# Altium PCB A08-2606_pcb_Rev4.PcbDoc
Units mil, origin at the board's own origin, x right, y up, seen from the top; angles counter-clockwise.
Board outline 1181.16 x 1930.8 mil, 6 copper layers (Top Electrical, Ground Plane (GND), Inner Layer 1, Inner Layer 2, Power Plane (VCC), Bottom Electrical), stack 51.068 mil thick; 77 components, 49 nets, 270 pads, 163 vias.
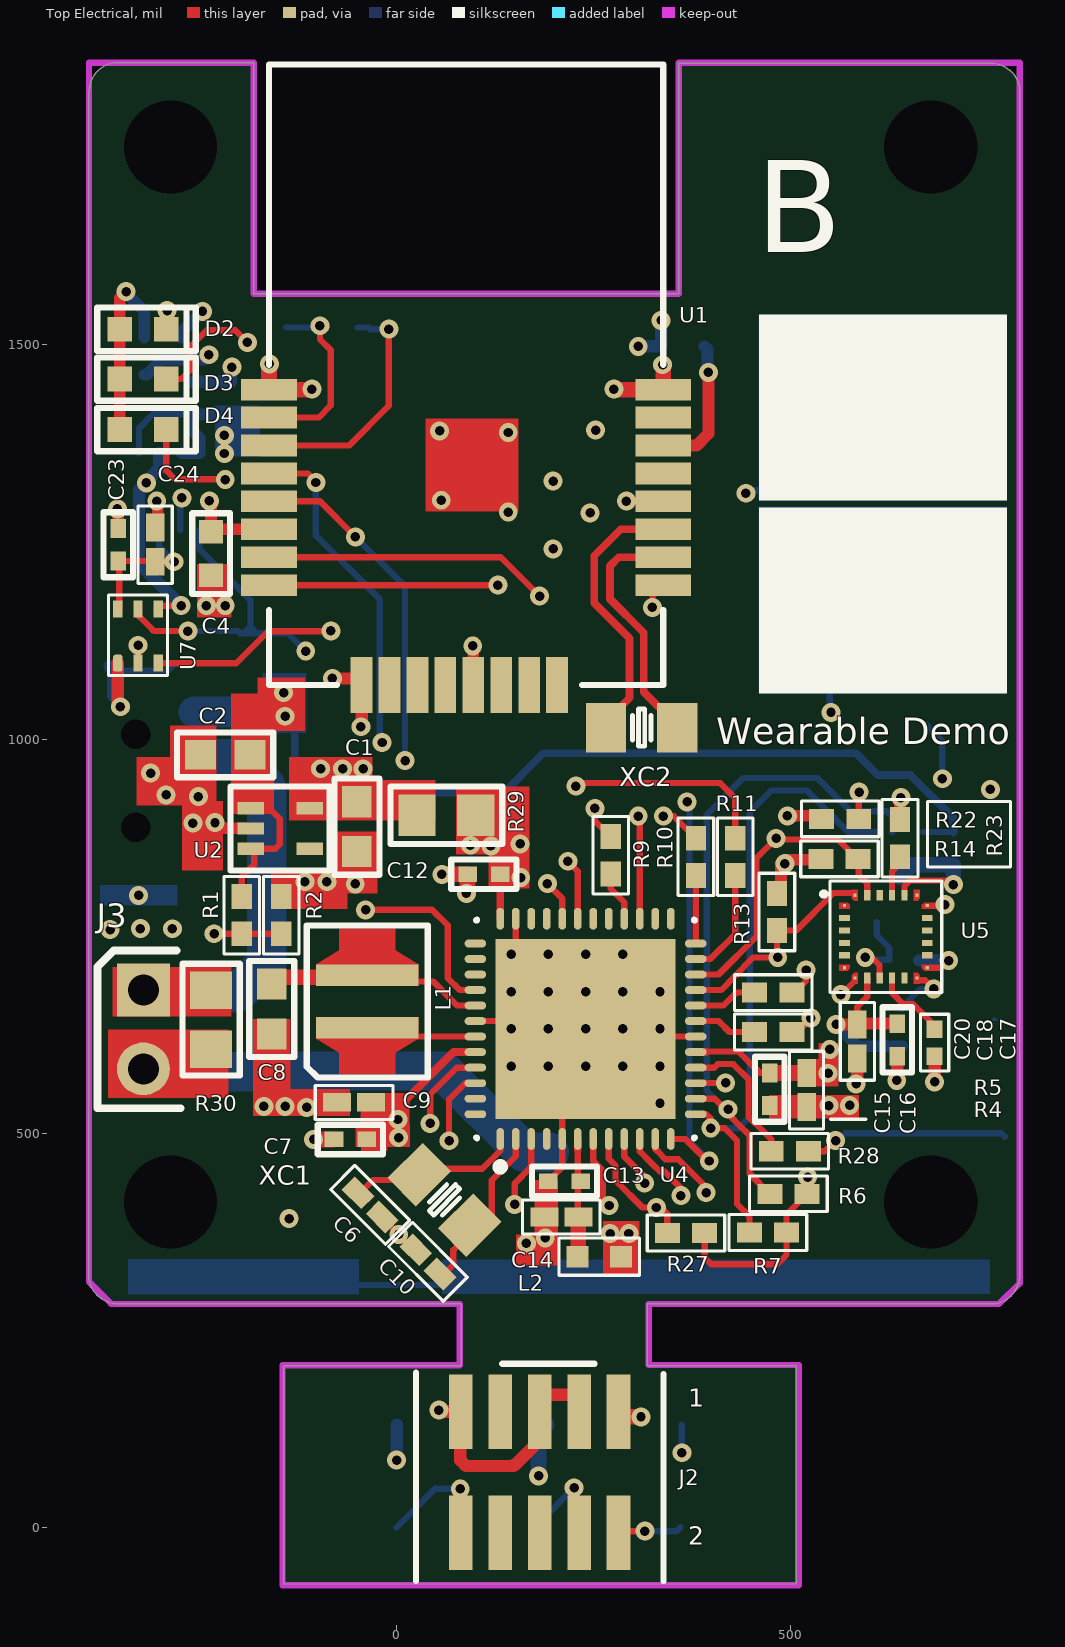
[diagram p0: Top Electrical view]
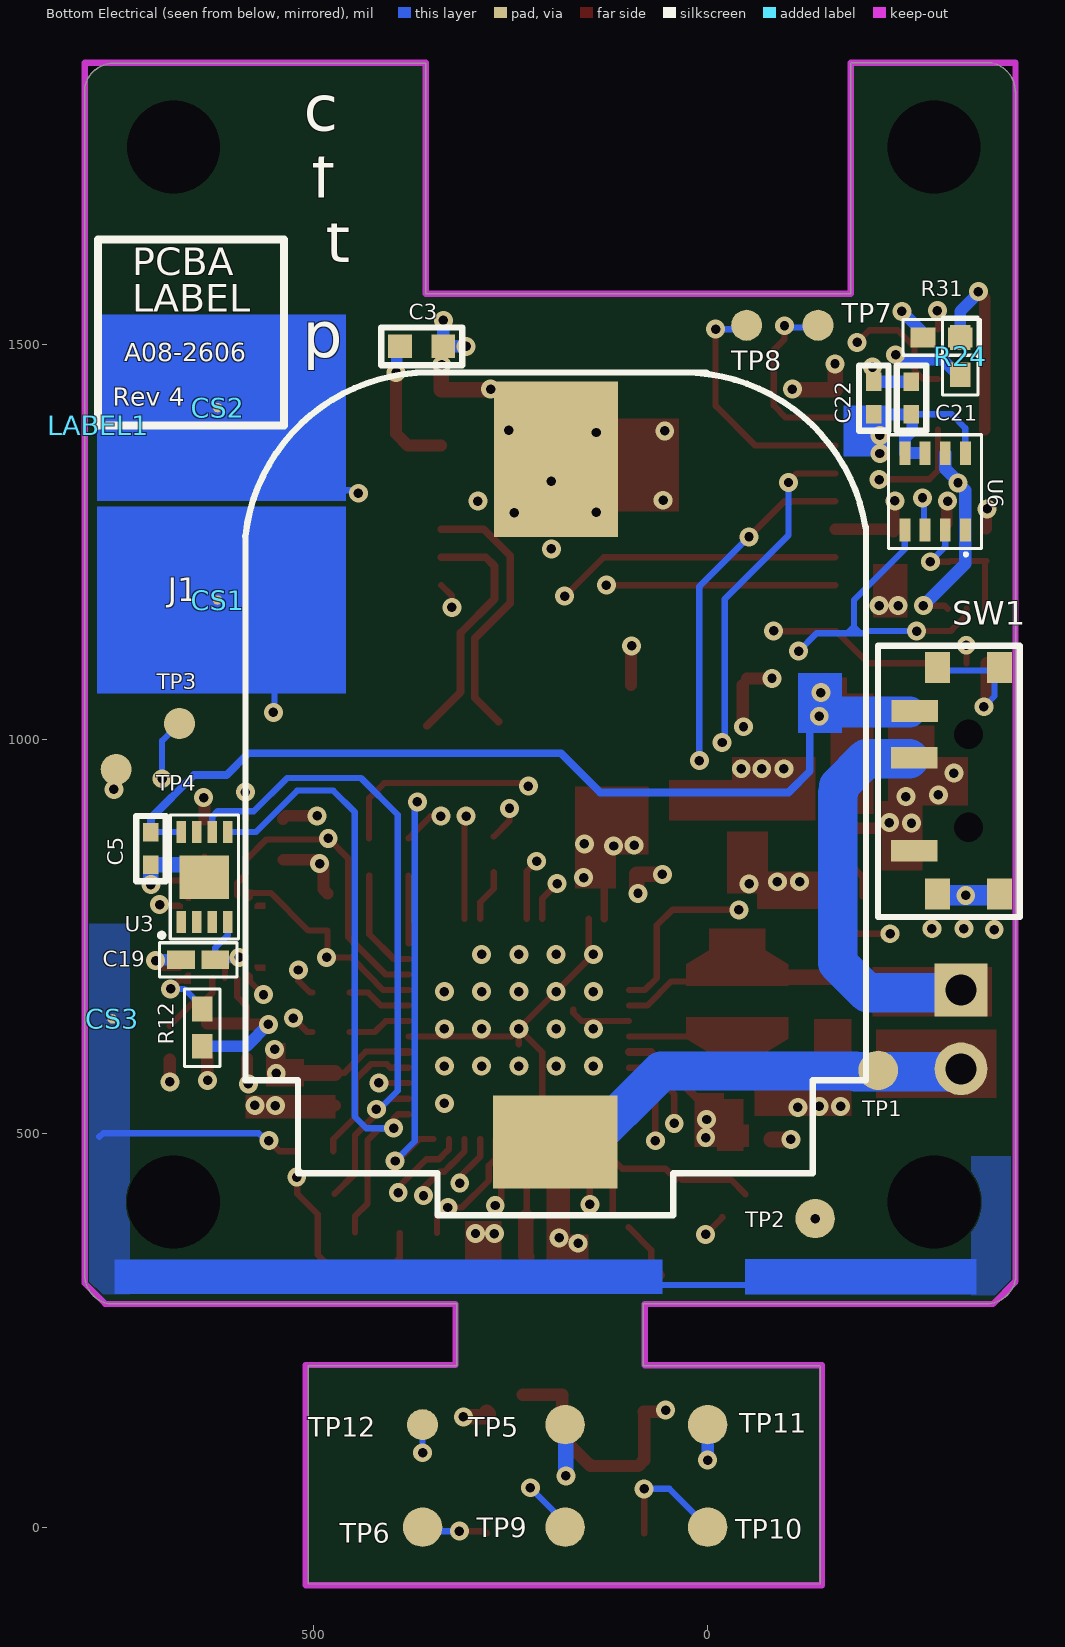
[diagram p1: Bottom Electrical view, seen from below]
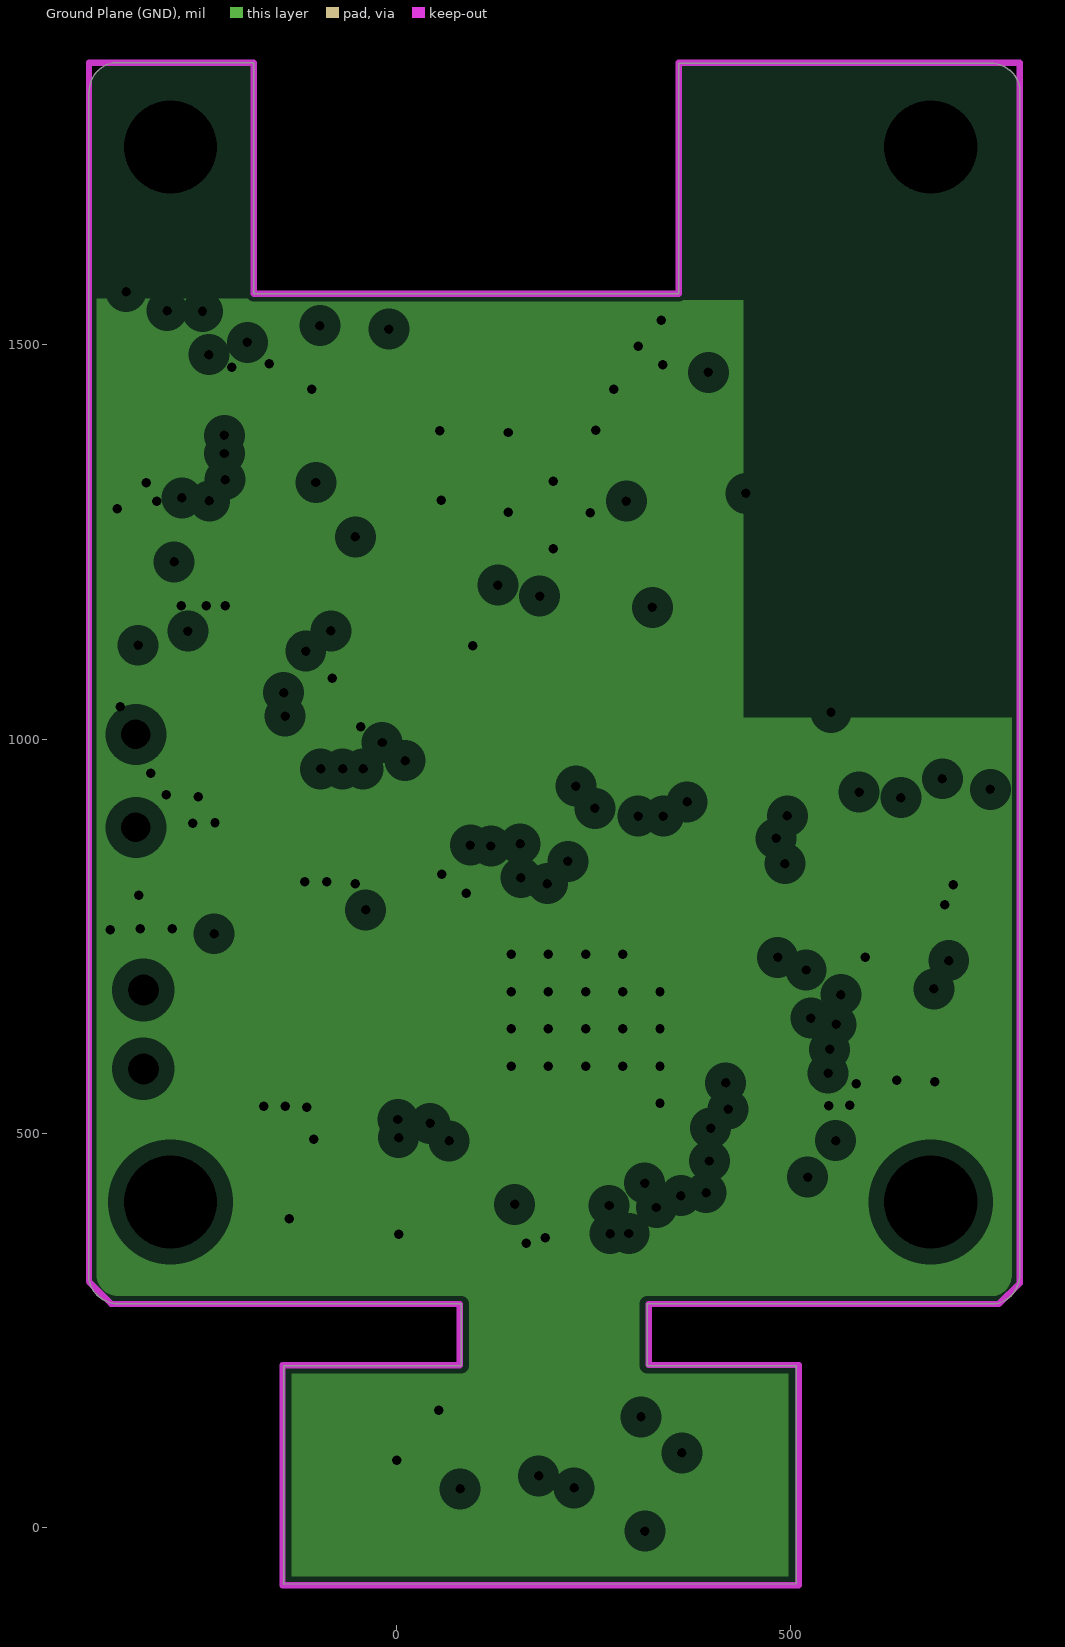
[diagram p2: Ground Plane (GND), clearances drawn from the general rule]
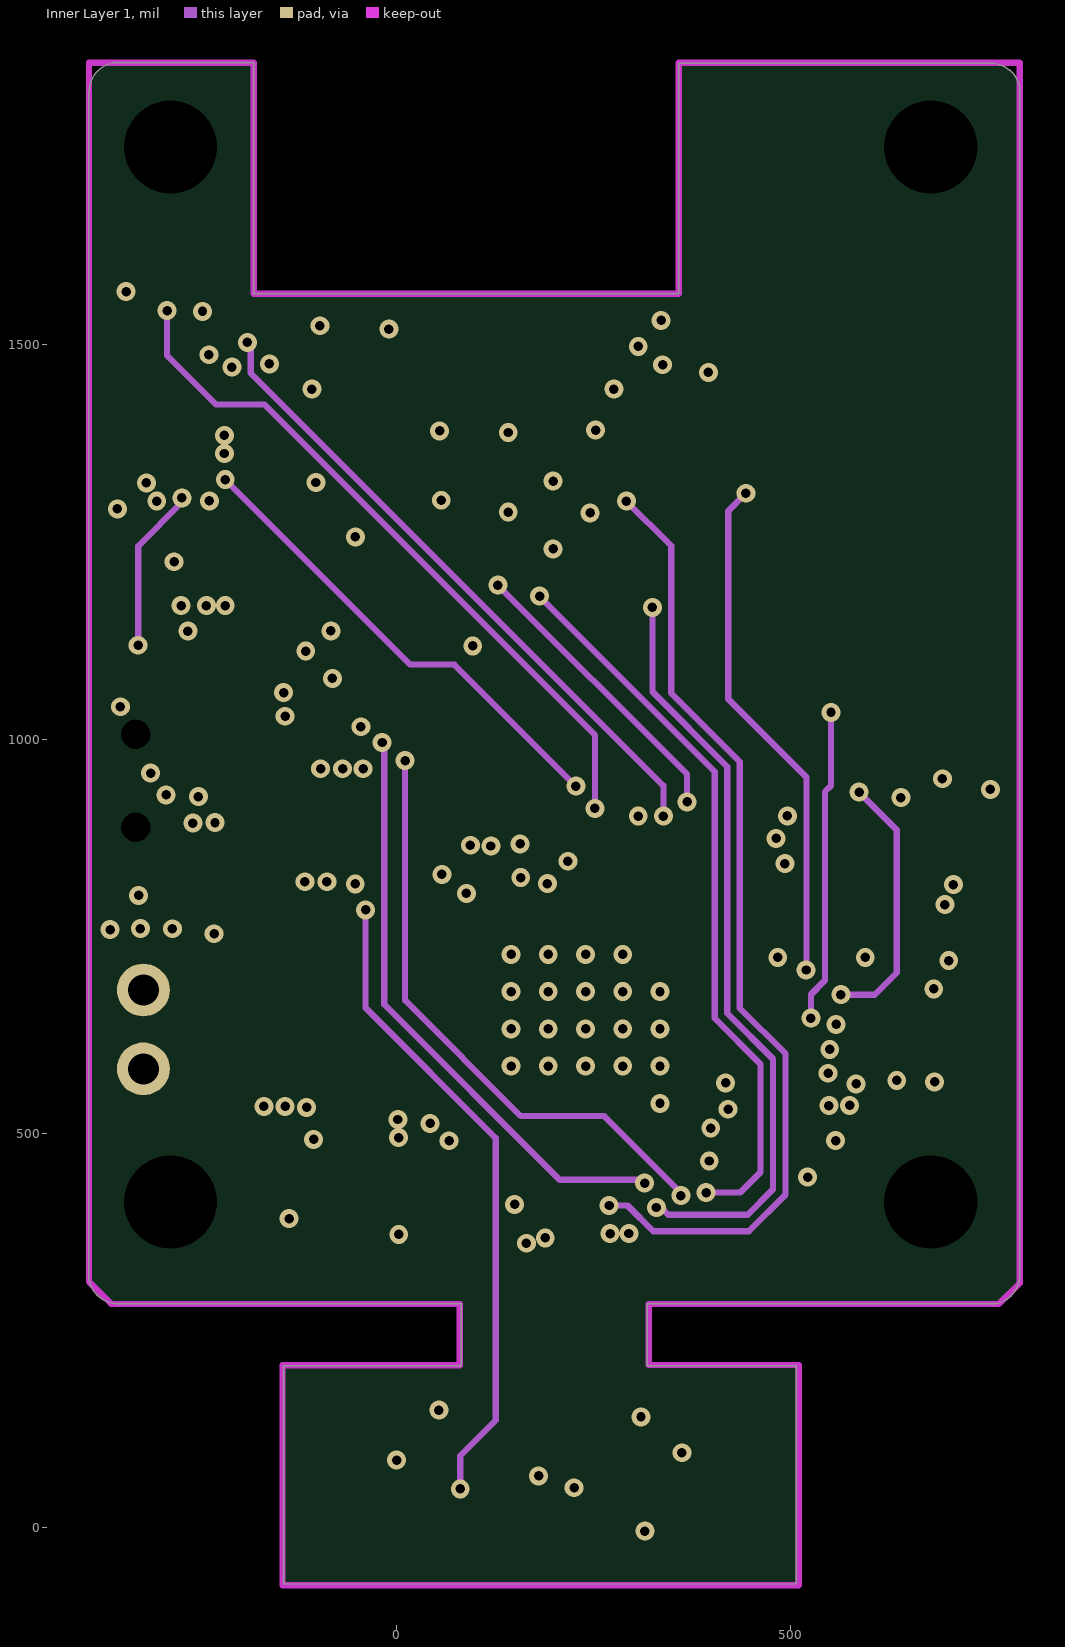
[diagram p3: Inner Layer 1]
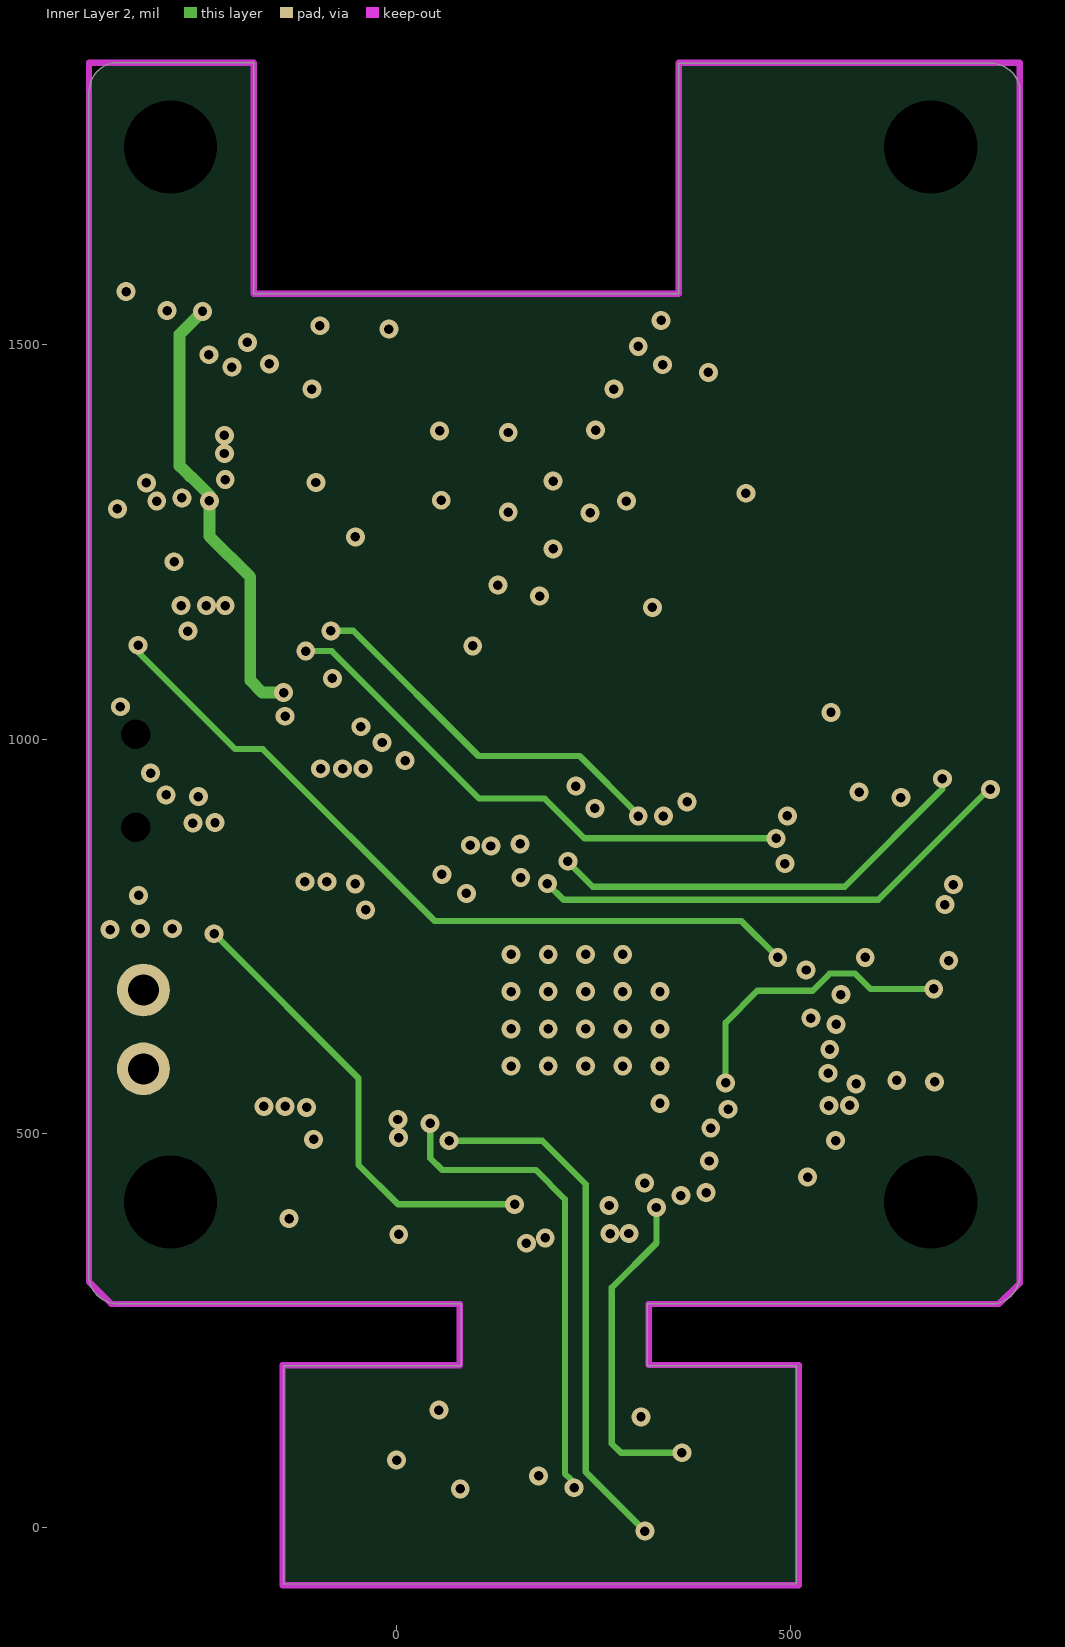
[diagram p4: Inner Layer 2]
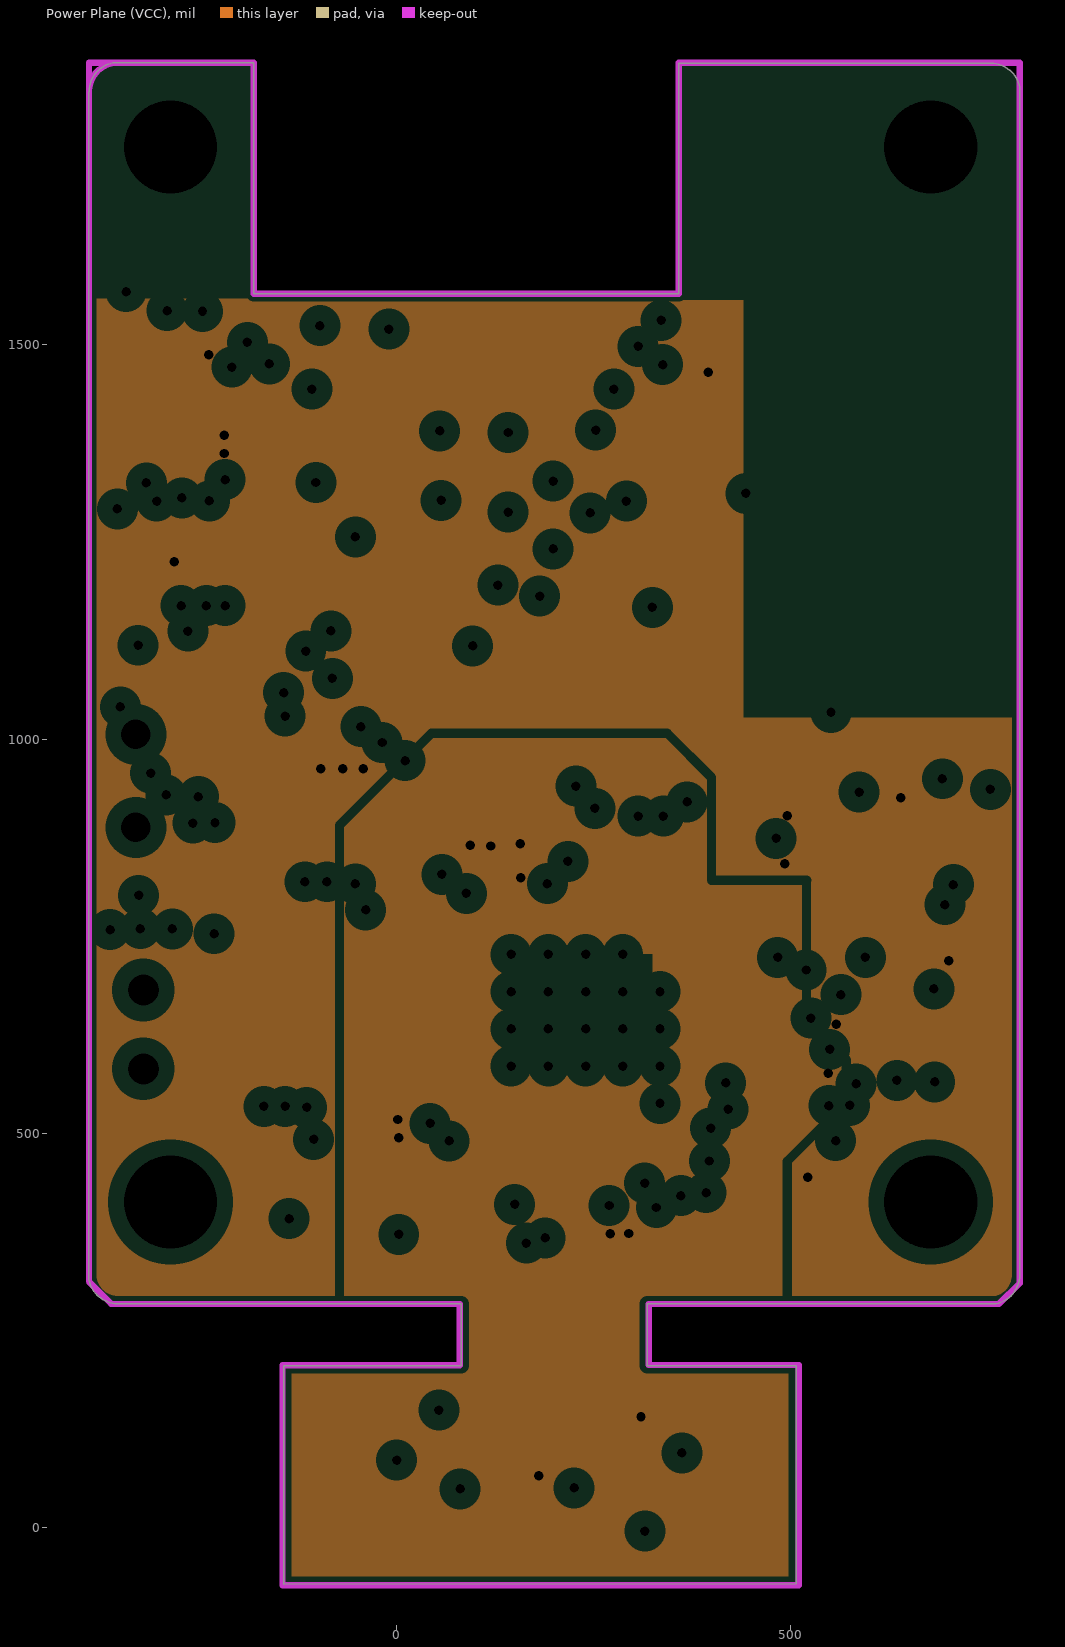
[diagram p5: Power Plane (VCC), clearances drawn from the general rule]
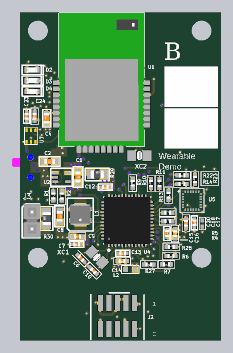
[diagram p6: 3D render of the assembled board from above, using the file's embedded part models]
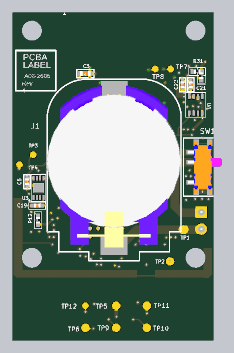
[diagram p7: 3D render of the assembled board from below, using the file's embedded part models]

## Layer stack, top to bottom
Top Solder: solder mask 0.4, Solder Resist, Dk 3.5
Top Electrical: signal copper 1.4
Dielectric 1: core 12.6, FR-4, Dk 4.8
Ground Plane (GND): plane copper 1.417, net GND
Dielectric 3: prepreg 5, Dk 4.2
Inner Layer 1: signal copper 1.417
Dielectric 6: core 10, Dk 4.2
Inner Layer 2: signal copper 1.417
Dielectric 5: prepreg 5, Dk 4.2
Power Plane (VCC): plane copper 1.417, net (Multiple Nets)
Dielectric 4: core 10, Dk 4.2
Bottom Electrical: signal copper 1.4
Bottom Solder: solder mask 0.4, Solder Resist, Dk 3.5

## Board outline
-143.03,-72.54 -143.03,204.72 81.89,204.72 81.89,283.46 -353.73,283.46 -354.22,283.57 cw(c-353.72,321.07) -390.5,313.71 -390.55,313.71 -390.55,1821.6 -390.39,1821.6 cw(c-352.89,1821.1) -360.25,1857.87 -360.25,1858.27 -181.56,1858.27 -181.56,1564.96 357.81,1564.96 357.81,1857.48 754.33,1857.48 754.28,1857.38 cw(c753.78,1819.88) 790.55,1827.23 790.61,1827.6 790.61,320.1 790.5,319.6 cw(c753,320.1) 760.36,283.32 760.61,283.46 318.11,283.46 318.11,204.72 506.93,204.72 506.93,-71.75

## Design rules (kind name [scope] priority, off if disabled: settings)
Clearance Clearance_1 [InComponent('SW1') vs (OnLayer('Keep-Out Layer'))] p1: gap=0
Clearance SW1 [InComponent('SW1') vs (OnLayer('Keep-Out Layer'))] p2: gap=5
Clearance Y9 [InNamedPolygon('PROX')] p3: gap=2
Clearance GYRO [HasFootprint('AP6-00470')] p4: gap=7.56
Clearance "LED CLEARENCE" [HasFootprint('LED')] p5: gap=1
Clearance [All] p6: gap=7.87
ComponentClearance [All] p1 off: gap=10 collisioncheckmode=3 verticalgap=10 showdistances=FALSE
HoleSize [All] p1 off: absolutevalues=TRUE maxlimit=137.8 minlimit=3.94 maxpercent=80.000 minpercent=20.000
MinimumSolderMaskSliver [All] p1 off: minsoldermaskwidth=10
PlaneClearance [All] p1: clearance=20
PlaneConnect [All] p1: planeconnectstyle=Direct reliefexpansion=20 reliefentries=4 reliefconductorwidth=10 reliefairgap=10
PolygonConnect [All] p1: connectstyle=Direct reliefconductorwidth=10 reliefentries=4 polygonreliefangle="90 Angle" airgapwidth=10
RoutingVias [All] p1: holewidth=12 width=24 viastyle="Through Hole" minholewidth=12 minwidth=24 maxholewidth=28 maxwidth=50
SilkToBoardRegionClearance [All] p1 off:
SilkToSilkClearance [All] p1 off: silktosilkclearance=10
SilkToSolderMaskClearance [IsPad] p1 off: minsilkscreentomaskgap=10 clearancetoexposedcopper=TRUE
SolderMaskExpansion [All] p1: expansion=4
Width [All] p1: maxlimit=100 minlimit=6 preferedwidth=8
22 further rules are at their usual default settings.

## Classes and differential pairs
component class "U_SAML21 Wearable Demo__BTLC_CRYPTO_PWR": C1 C2 C3 C4 C5 J1 J3 R1 R2 R27 R30 SW1 TP1 TP2 TP7 TP8 TP12 U1 U2 U3 XC2
component class "U_SAML21 Wearable Demo__MCU&Touch": C6 C7 C8 C9 C10 C12 C13 C14 C15 C16 CS1 CS2 CS3 D2 D3 D4 J2 L1 L2 R4 R5 R6 R7 R9 R10 R11 R24 R28 R29 R31 TP3 TP4 TP5 TP6 TP9 TP10 TP11 U4 XC1
component class "U_SAML21 Wearable Demo__MEMS_Sensors": C17 C18 C19 C20 C21 C22 C23 C24 R12 R13 R14 R22 R23 TP16 TP17 TP18 TP19 TP20 U5 U6 U7
component class "SAML21 Wearable Demo_Top Level": LABEL1

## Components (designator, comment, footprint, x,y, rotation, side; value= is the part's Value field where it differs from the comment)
C1 "CAP-NONPOL" AP1-00002 -50.5,888.93 r270 top
C2 "CAP-NONPOL" AP1-00002 -217.55,979.93 r180 top
C3 "Close to Pin22(VDDIO)of U101" AP1-00039 362.95,1498.27 r0 bottom
C4 "Close to Pin22(VDDIO)of U101" AP1-00039 -235.55,1235.43 r90 top
C5 "CAP-NONPOL" AP1-00038 706.45,860.93 r90 bottom
C6 "CAP-NONPOL" AP1-00001 -33.71,408.91 r315 top
C7 "CAP-NONPOL" AP1-00038 -58.83,491.93 r0 top
C8 "CAP-NONPOL" AP1-00002 -158.5,657.43 r270 top
C9 "Recommended by Escatec. No datasheet available yet." AP1-00001 -54.15,538.93 r180 top
C10 "CAP-NONPOL" AP1-00001 39.61,336.6 r135 top
C12 "CAP-NONPOL" AP1-00038 110.61,828.48 r0 top
C13 "CAP-NONPOL" AP1-00038 212.85,438.8 r0 top
C14 "Recommended by Escatec. No datasheet available yet." AP1-00001 208.95,393.48 r180 top
C15 "CAP-NONPOL" AP1-00038 473.2,555.65 r90 top
C16 "Recommended by Escatec. No datasheet available yet." AP1-00001 520.05,554.66 r270 top
C17 "For Zigbit" AP1-00034 682.47,614.72 r270 top
C18 "CAP-NONPOL" AP1-00038 635.12,618.29 r90 top
C19 "Recommended by Escatec. No datasheet available yet." AP1-00001 646.45,719.93 r180 bottom
C20 "Recommended by Escatec. No datasheet available yet." AP1-00001 584.5,616.27 r270 top
C21 "CAP-NONPOL" AP1-00038 -258.55,1432.6 r270 bottom
C22 "CAP-NONPOL" AP1-00038 -210.55,1432.6 r270 bottom
C23 "CAP-NONPOL" AP1-00038 -353.29,1246.49 r270 top
C24 "Recommended by Escatec. No datasheet available yet." AP1-00001 -306.5,1246.58 r90 top
CS1 "PCB implemented component only. Not to be mounted." AP8-01013#1 50076.87,50856.38 r0 top
CS2 "PCB implemented component only. Not to be mounted." AP8-01013#1 50076.87,51100.47 r0 top
CS3 "PCB implemented component only. Not to be mounted." AP8-01013#2 50370.43,50204.27 r0 top
D2 "APT1608LSECK-J3-PRV" AP4-00017 -321.91,1520 r180 top
D3 "APT1608LSYCK-J3-PRV" AP4-00017 -321.91,1456.71 r180 top
D4 "APT1608LSECK-J4-PRV" AP4-00017 -321.91,1392.6 r180 top
J1 "Element14-Order Code: 2064724" AP8-01011 192.91,921.9 r270 bottom
J2 "HEADER 2x5" AP8-00109 181.45,69.67 r180 top locked
J3 "#NAME?" AP8-00733 -321.39,631.6 r270 top locked
L1 "INDUCTOR" AP3-00115 -37.43,666.99 r90 top
L2 "" AP3-00005 257.01,343.27 r180 top
LABEL1 "PCBA_LABEL" AP9-00049 773.61,1397.6 r180 bottom
R1 "R2" AP2-00000 -196.55,776.55 r270 top
R2 "R2" AP2-00000 -146.55,776.55 r90 top
R4 "R2" AP2-00000 477.78,628.28 r0 top
R5 "R2" AP2-00000 477.78,678.28 r0 top
R6 "R2" AP2-00000 497.07,422.93 r180 top
R7 "R2" AP2-00000 471.07,373.93 r180 top
R9 "R2" AP2-00000 271.5,852.55 r90 top
R10 "R2" AP2-00000 379.61,850.48 r90 top
R11 "R2" AP2-00000 429.61,850.48 r90 top
R12 "R2" AP2-00000 641.37,633.88 r90 bottom
R13 "R2" AP2-00000 482.45,780.55 r270 top
R14 "R2" AP2-00000 561.83,847.93 r0 top
R22 "R2" AP2-00000 562.61,898.6 r180 top
R23 "R2" AP2-00000 638.61,874.22 r90 top
R24 "R2" AP2-00000 -320.39,1485.92 r270 bottom
R27 "R2" AP2-00000 367.07,373.27 r180 top
R28 "R2" AP2-00000 498.83,476.93 r0 top
R29 "R2" AP2-00002 63.01,903.27 r0 top
R30 "R2" AP2-00002 -235.5,643.93 r90 top
R31 "R2" AP2-00000 -296.77,1509.54 r0 bottom
SW1 "SW_SPDT" AP8-01012 -261.99,976.38 r90 bottom locked
TP1 "TESTPOINT" AP8-00010#1 -216.39,579.6 r180 bottom
TP2 "TESTPOINT" AP8-00010#1 -136.39,391.6 r0 bottom
TP3 "TESTPOINT" AP8-00010#2 670.28,1019.69 r180 bottom
TP4 "TESTPOINT" AP8-00010#2 750.59,961.42 r180 bottom
TP5 "TESTPOINT" AP8-00010#3 184,130 r90 bottom
TP6 "TESTPOINT" AP8-00010#1 361.81,0 r90 bottom
TP7 "TESTPOINT" AP8-00010#2 -139.96,1525 r90 bottom
TP8 "TESTPOINT" AP8-00010#2 -49.41,1525 r90 bottom
TP9 "TESTPOINT" AP8-00010#1 180.91,0 r90 bottom
TP10 "TESTPOINT" AP8-00010#1 0,0 r90 bottom
TP11 "TESTPOINT" AP8-00010#1 0,130 r90 bottom
TP12 "TESTPOINT" AP8-00010#2 361.81,130 r90 bottom
U1 "BTLC1000 module" AP9-00141 338.13,1195.28 r90 top locked
U2 "NCP512" AP6-00012 -147.96,886.52 r0 top
U3 "ATECC508A-I2C" AP6-00409 638.61,824.84 r90 bottom
U4 "SAML21G18BM" AP6-00322 239.58,632.3 r90 top
U5 "BHI160" AP6-00470 620.66,749.17 r0 top locked
U6 "Operating range -40â€|+85 Â°C, 0â€|100 % rel. humidity, 300â€|1100 hPa" AP6-00469 -288.55,1313.93 r270 bottom
U7 "VEML6030" PCBComponent_1 -353.88,1096.22 r90 top
XC1 "power = drive level" AP7-00048 60.45,415.46 r315 top
XC2 "power = drive level" AP7-00048 311.16,1014.48 r180 top

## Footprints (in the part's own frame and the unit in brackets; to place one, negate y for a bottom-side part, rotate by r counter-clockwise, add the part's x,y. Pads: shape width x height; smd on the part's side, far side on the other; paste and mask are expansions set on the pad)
AP1-00001 [mm] "Standard 0402 SMD capacitor footprint"
  rect 0.9x0.6 smd: 1(-0.55,0) 2(0.55,0)
  silkscreen extent -1.25,-0.55 1.25,0.55, body extent -0.5,-0.3 0.5,0.3, height 0.2
AP1-00002 [mm]
  rect 1x0.95 smd: 1(-0.8,0) 2(0.8,0)
  silkscreen extent -1.55,-0.73 1.55,0.72, body extent -0.8,-0.4 0.8,0.4, height 0.3
AP1-00034 [mm] "0402_SMD"
  rect 0.56x0.51 smd paste+0 mask+0.05: 1(-0.435,0) 2(0.435,0)
  silkscreen extent -0.91,-0.46 0.91,0.46
AP1-00038 [mm] "Generic pad 0402, spacing 0.45mm"
  rect 0.6x0.5 smd: 1(-0.525,0) 2(0.525,0)
  silkscreen extent -1.05,-0.47 1.05,0.47, body extent -0.5,-0.3 0.5,0.3, height 0.2
AP1-00039 [mil] "Capacitor 0603 Hight 0.8mm"
  rect 30x30 smd: 1(-27.5,0) 2(27.5,0)
  silkscreen extent -52,-24 51,24, body extent -31,-16 32,16, height 12
AP2-00000 [mm] "Standard 0402 SMD resistor footprint"
  rect 0.8x0.65 smd: 1(-0.6,0) 2(0.6,0)
  silkscreen extent -1.25,-0.58 1.25,0.58, body extent -0.5,-0.3 0.5,0.3, height 0.2
AP2-00002 [mm]
  rect 1.2x1.35 smd: 1(-0.95,0) 2(0.95,0)
  silkscreen extent -1.8,-0.92 1.8,0.92, body extent -1,-0.62 1,0.63, height 0.78
AP3-00005 [mm]
  rect 0.7x0.7 smd: 1(-0.7,0) 2(0.7,0)
  silkscreen extent -1.3,-0.6 1.3,0.6, body extent -0.82,-0.41 0.83,0.41, height 0.8
AP3-00115 [mm] "SMD Chip Inductor LQH3NPN_J0 Series (1212 Size)"
  rect 0.7x3.3 smd: 1(-0.85,0) 2(0.85,0)
  Top Electrical region: -0.5,1.65 -1.2,1.65 -1.65,0.9 -1.65,-0.9 -1.2,-1.65 -0.5,-1.65
  Top Electrical region: 0.5,-1.65 1.2,-1.65 1.65,-0.9 1.65,0.9 1.2,1.65 0.5,1.65
  Top Electrical region: -1.625,0.9 -2.35,0.9 -2.35,-0.9 -1.625,-0.9
  Top Electrical region: 1.625,-0.9 2.35,-0.9 2.35,0.9 1.625,0.9
  silkscreen extent -2.45,-1.95 2.45,1.95, body extent -1.5,-1.5 1.5,1.5, height 1.1
AP4-00017 [mm]
  rect 0.8x0.8 smd: 1(-0.75,0) 2(0.75,0)
  silkscreen extent -1.7,-0.7 1.48,0.7, body extent -0.84,-0.35 0.81,0.37, height 0.68
AP6-00012 [mm]
  rect 0.85x0.4 smd: 1(-0.95,0.65) 2(-0.95,0) 3(-0.95,-0.65) 4(0.95,-0.65) 5(0.95,0.65)
  silkscreen extent -1.6,-1.35 1.6,1.35, body extent -0.67,-1.1 0.67,1.1, height 1.1
AP6-00322 [mm] "QFN48_7x7mm_5.8x5.8mm_Paddle"
  oval 0.7x0.25 smd: 1(-3.55,2.75) 2(-3.55,2.25) 3(-3.55,1.75) 4(-3.55,1.25) 5(-3.55,0.75) 6(-3.55,0.25) 7(-3.55,-0.25) 8(-3.55,-0.75) 9(-3.55,-1.25) 10(-3.55,-1.75) 11(-3.55,-2.25) 12(-3.55,-2.75) 25(3.55,-2.75) 26(3.55,-2.25) 27(3.55,-1.75) 28(3.55,-1.25) 29(3.55,-0.75) 30(3.55,-0.25) 31(3.55,0.25) 32(3.55,0.75) 33(3.55,1.25) 34(3.55,1.75) 35(3.55,2.25) 36(3.55,2.75)
  oval 0.25x0.7 smd: 13(-2.75,-3.55) 14(-2.25,-3.55) 15(-1.75,-3.55) 16(-1.25,-3.55) 17(-0.75,-3.55) 18(-0.25,-3.55) 19(0.25,-3.55) 20(0.75,-3.55) 21(1.25,-3.55) 22(1.75,-3.55) 23(2.25,-3.55) 24(2.75,-3.55) 37(2.75,3.55) 38(2.25,3.55) 39(1.75,3.55) 40(1.25,3.55) 41(0.75,3.55) 42(0.25,3.55) 43(-0.25,3.55) 44(-0.75,3.55) 45(-1.25,3.55) 46(-1.75,3.55) 47(-2.25,3.55) 48(-2.75,3.55)
  rect 5.8x5.8 smd: 49(0,0)
  silkscreen extent -4.57,-3.52 3.52,3.52, body extent -3.51,-3.51 3.51,3.51, height 0.78
AP6-00409 [mm]
  rect 0.7x0.3 smd mask+0.075: 1(-1.45,0.75) 2(-1.45,0.25) 3(-1.45,-0.25) 4(-1.45,-0.75) 5(1.45,-0.75) 6(1.45,-0.25) 7(1.45,0.25) 8(1.45,0.75)
  rect 1.4x1.6 smd paste-0.025 mask+0.075: 9(0,0)
  silkscreen extent -2,-1.1 2,1.45, body extent -1.55,-1.05 1.55,1.05, height 0.6
AP6-00469 [mm] "LGA_2.5 mm x 2.5 mm x 0.93 mm metal lid"
  rect 0.75x0.35 smd: 1(1.235,0.975) 2(1.235,0.325) 3(1.235,-0.325) 4(1.235,-0.975) 5(-1.235,-0.975) 6(-1.235,-0.325) 7(-1.235,0.325) 8(-1.235,0.975)
  silkscreen extent -1.84,-1.5 2.07,1.5, body extent -1.25,-1.25 1.25,1.25, height 1
AP6-00470 [mm] "LGA_24_3.0X3.0X.95"
  rect 0.1x0.1 smd mask+0: 1(-1.335,1) 6(-1.335,-1) 7(-1,-1.335) 12(1,-1.335) 13(1.335,-1) 18(1.335,1) 19(1,1.335) 24(-1,1.335)
  rect 0.35x0.2 smd mask+0: 2(-1.335,0.6) 3(-1.335,0.2) 4(-1.335,-0.2) 5(-1.335,-0.6) 14(1.335,-0.6) 15(1.335,-0.2) 16(1.335,0.2) 17(1.335,0.6)
  rect 0.2x0.35 smd mask+0: 8(-0.6,-1.335) 9(-0.2,-1.335) 10(0.2,-1.335) 11(0.6,-1.335) 20(0.6,1.335) 21(0.2,1.335) 22(-0.2,1.335) 23(-0.6,1.335)
  Top Electrical region: -1.1,-1.51 -1.1,-1.236 -1.024,-1.16 -0.9,-1.16 -0.9,-1.51
  Top Electrical region: -1.51,-1.1 -1.236,-1.1 -1.16,-1.024 -1.16,-0.9 -1.51,-0.9
  Top Electrical region: 1.1,-1.51 1.1,-1.236 1.024,-1.16 0.9,-1.16 0.9,-1.51
  Top Electrical region: 1.51,-1.1 1.236,-1.1 1.16,-1.024 1.16,-0.9 1.51,-0.9
  Top Electrical region: 1.51,1.1 1.236,1.1 1.16,1.024 1.16,0.9 1.51,0.9
  Top Electrical region: 1.1,1.51 1.1,1.236 1.024,1.16 0.9,1.16 0.9,1.51
  Top Electrical region: -1.1,1.51 -1.1,1.236 -1.024,1.16 -0.9,1.16 -0.9,1.51
  Top Electrical region: -1.51,1.1 -1.236,1.1 -1.16,1.024 -1.16,0.9 -1.51,0.9
  silkscreen extent -2.03,-1.8 1.8,1.8, body extent -1.55,-1.55 1.55,1.55, height 1
AP7-00048 [mm] "CFPX  32.768kHz Crystal mini"
  rect 1.3x1.6 smd: 1(-1.143,0) 2(1.157,0)
  silkscreen extent -0.29,-0.6 0.31,0.6, body extent -1.6,-0.77 1.6,0.72, height 0.77
AP8-00010#1 [mil] "Testpad 50mil"
  round 50 smd paste-25: 1(0,0)
AP8-00010#2 [mil] "Testpad 50mil"
  round 39.37 smd paste-25: 1(0,0)
AP8-00010#3 [mil] "Testpad 50mil"
  round 50 smd paste-25: 1(0,-3.09)
AP8-00109 [mm]
  rect 0.76x2.4 smd: 1(-2.54,-1.95) 2(-2.54,1.95) 3(-1.27,-1.95) 4(-1.27,1.95) 5(0,-1.95) 6(0,1.95) 7(1.27,-1.95) 8(1.27,1.95) 9(2.54,-1.95) 10(2.54,1.95)
  silkscreen extent -3.99,-3.21 3.99,3.5, body extent -3.81,-3 3.81,3
AP8-00733 [mm] "Pin header 1x2 Pin in Paste"
  rect 1.7x1.7 / inner round 1.7 / far side rect 1.7x1.7 hole 1: 1(-1.27,0)
  rect 2.1x2.1 on Top Paste: 1(-1.27,0) 2(1.27,0)
  round 1.7 hole 1: 2(1.27,0)
  silkscreen extent -2.54,-1.48 2.54,1.19, body extent -2.54,-1.27 2.54,1.27, height 8.38
AP8-01011 [mm] "Coin cell Battery Holder 24.9X15.6X5.3"
  rect 5x4 smd mask+0: 1(-11,0.012)
  rect 3x4 smd mask+0: 2(11,-0.012)
  silkscreen extent -13.8,-10 13.36,10, body extent -12.88,-10.01 11.38,9.96, height 5.4
AP8-01012 [mm]
  round 0.5 hole 0.95 mask+0: 0(-2.25,-1.75) 0(0.75,-1.75)
  rect 0.7x1.5 smd mask+0: 1(0,0) 2(1.5,-0.023) 3(-3,0)
  rect 1x0.8 smd mask+0: 4(-4.4,-2.75) 4(-4.4,-0.75) 4(2.9,-0.75) 4(2.9,-2.75)
  silkscreen extent -5.13,-3.4 3.61,1.17, body extent -4.6,-4.53 3.1,0.47, height 1.4
AP8-01013#1 [mil] "Capacitive Touch Button 8x6MM"
  round 12 smd far side paste-12 mask+0: 1(-49455,-49680)
  Bottom Electrical region: -49617.48,-49561.89 -49617.48,-49798.11 -49302.52,-49798.11 -49302.52,-49561.89
AP8-01013#2 [mil] "Capacitive Touch Button 8x6MM"
  round 12 smd far side paste-12 mask+0: 1(-49614.98,-49559.39)
  Bottom Electrical region: -49617.48,-49561.89 -49617.48,-49561.89 -49612.48,-49556.89 -49607.48,-49561.89
AP9-00049 [mil] "Placement area for 6x6mm sticker"
  silkscreen extent 0,0 236,236
AP9-00141 [mm] "BTLC 1000 Module"
  rect 0.7x1.8 smd: 1(6.3,12.7) 2(5.4,12.7) 3(4.5,12.7) 4(3.6,12.7) 5(2.7,12.7) 6(1.8,12.7) 7(0.9,12.7) 8(0,12.7) 17(0,0) 18(0.9,0) 19(1.8,0) 20(2.7,0) 21(3.6,0) 22(4.5,0) 23(5.4,0) 24(6.3,0)
  rect 1.8x0.7 smd: 9(-3.22,9.72) 10(-3.22,8.82) 11(-3.22,7.92) 12(-3.22,7.02) 13(-3.22,6.12) 14(-3.22,5.22) 15(-3.22,4.32) 16(-3.22,3.42)
  Top Electrical region: 2.37,4.659 5.37,4.659 5.37,7.659 2.37,7.659
  silkscreen extent -3.22,0 16.78,12.7, body extent -3.22,0 16.78,12.7, height 4.4
PCBComponent_1 [mm]
  rrect50% 0.2x0.2 on Top Overlay paste-0.305 mask+0: 1(0,0.5)
  rrect50% 0.55x0.3 smd paste-0.305 mask+0: 1(0,0)
  rect 0.55x0.3 smd paste-0.305 mask+0: 2(0,-0.65) 3(0,-1.3) 4(1.75,-1.3) 5(1.75,-0.65) 6(1.75,0)
  silkscreen extent -0.4,-1.6 2.2,0.3

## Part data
C1 C2 C8: library part A01-0268, "Ceramic capacitor, SMD 0603, X5R, 6.3V, ±10%"
C3 C4: library part A01-0491, "Ceramic capacitor, SMD 0603, X5R, 16V, 10UF ± 20% (High Density)"
C5 C7 C12 C13 C15 C18 C21 C22 C23: library part A01-0352, "Ceramic capacitor, SMD 0402, X7R, 16V, +/-10% (de19761)"
C6 C10: library part A01-0013, "Ceramic capacitor, SMD 0402, NP0, 50V, +/-5%"
C9 C14 C16 C19 C20 C24: library part A01-0347, "Ceramic capacitor, SMD 0402, X5R, 6.3V, +/-20% (de33687)"
C17: library part A01-0334, "Ceramic Capacitors - SMD0402 6.3V, 470nF, 10%, X5R"
CS1 CS2 CS3: library part A08-2605, "Capacitive Touch Button 8x6MM"
D2: library part A10-0187, "LED RED CLEAR 0603 SMD_Rectangle with Flat Top, 1.10mm x 0.80mm"
D3: library part A10-0188, "1.85V_Rectangle with Flat Top, 1.10mm x 0.80mm_LED YELLOW CLEAR 0603 SMD"
D4: library part A10-0189, "1.8V_LED ORANGE CLEAR 0603 SMD_1.60mm L x 0.80mm W"
J1: library part A08-2603, "Battery Holder, SMT, 20 mm"
J2: library part A08-0022, "2x5 pin header, 1.27mm pitch, SMD"
J3: library part A08-1754, "1x2 pin header, 2.54mm pitch, Pin-in-Paste THM"
L1: library part A03-0191, "10uH power inductor, Isat = 560mA , Itemp = 710mA, Rdc = 0.360ohm"
L2: library part A03-0035, "SMD RF inductor 0603. Z=470Ohm (@100MHz), Max R(dc)=0.65Ohm, Max current=1A"
LABEL1: library part A09-0612, "PCBA identification label PP Top White Gloss"
R1 R2 R6 R7 R12 R13 R14 R22 R23: library part A02-0228, "Thick film resistor, SMD 0402, 1/16W, 1%"
R4 R5 R28: library part A02-0212, "Thick film resistor, SMD 0402, 1/16W, 1%"
R9 R10 R11: library part A02-0206, "Thick film resistor, SMD 0402, 1/16W, 1%"
R24 R31: library part A02-0163, "RES 0.0 OHM 1/16W 0402 SMD"
R27: library part A02-0260, "Thick film resistor, SMD 0402, 1/16W, 1%"
R29 R30: library part A02-0285, "Thick film resistor, SMD 0805, 0.125W, 1%"
SW1: library part A08-2604, "Slide Switches SPDT HORZ GRND 1.5mm"
TP1 TP2 TP3 TP4 TP5 TP6 TP7 TP8 TP9 TP10 TP11 TP12: library part A08-0004, "Single SMD testpad"
U1: library part A06-1298, "Bluetooth module, 24pin, chip Antenna, with shield, with MAC"
U2: library part A06-1426, "1.8V 80 mA CMOS Low Iq Voltage Regulator"
U3: library part A06-1281, "ATECC508A with an I2C Interface and a 8 Pin UDFN Package with Paddle"
U4: library part A06-1358, "Atmel 32-bit RISC MCU 48pin QFN"
U5: library part A06-1427, "Ultra-low power sensor hub inc.integrated IMU(GYRO)"
U6: library part A06-1425, "Humidity and pressure sensor"
U7: "IC,Sensor: UV + ALS"
XC1 XC2: library part A07-0056, "32.768kHz KX-327NHT, 3.2 x 1.5 mm SMD 20ppm (de19774)"

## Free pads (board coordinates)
  round 0 hole 118.11 unplated mask+0: MH(-286.96,412.6) MH(-286.95,1751.18) MH(677.61,412.6) MH(677.61,1751.18)

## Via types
v1: diameter 24, hole 12, Top Electrical to Bottom Electrical, tented both sides, 143 vias
v2: diameter 24, hole 12, Top Electrical to Bottom Electrical, tented top, 20 vias

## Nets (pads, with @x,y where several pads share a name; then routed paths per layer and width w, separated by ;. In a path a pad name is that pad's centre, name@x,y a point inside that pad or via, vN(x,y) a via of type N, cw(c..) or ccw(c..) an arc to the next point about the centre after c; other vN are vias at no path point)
BAT_SENSE: R1.2 R2.1 U4.3 | length 763.6
  Top Electrical w8: v1(-231.55,752.93) R1.2 R2.1@-147.55,752.93 ; v1(149.61,409.6) 149.61,436.03 170.68,457.11 U4.3
  Inner Layer 2 w8: v1(-231.55,752.93) -48.55,569.93 -48.55,459.76 1.61,409.6 v1(149.61,409.6)
BLE_CTS_MCU_RTS: U1.7 U4.11 | length 1394.9
  Top Electrical w8: U1.7 132.01,1230.71 v1(181.45,1181.27) ; U4.11 328.17,479.61 330.43,477.35 331.06,477.35 331.06,476.72 340.89,466.88 346.53,466.88 357.09,466.88 392.61,431.36 v1(392.61,424.6)
  Inner Layer 1 w8: v1(181.45,1181.27) 181.45,1180.37 403.45,958.37 403.45,645.66 461.64,587.46 461.64,450.46 435.78,424.6 v1(392.61,424.6)
BLE_EN: R27.2 TP12.1 U1.17 U4.8 | length 1617
  Top Electrical w8: U4.8 269.11,467.53 273.44,463.2 273.39,463.14 277.73,458.8 277.73,439.71 311.84,405.6 v1(329.61,405.6) 335.61,405.6 343.45,397.76 R27.2 ; v1(324.5,1166.93) 324.5,1181.65 U1.17
  Inner Layer 1 w8: v1(324.5,1166.93) 324.5,1059.76 419.57,964.69 419.57,853 419.5,852.93 419.5,652.05 477.52,594.04 477.52,428.65 445.44,396.57 344.64,396.57 335.61,405.6 v1(329.61,405.6)
  Inner Layer 2 w8: v1(329.61,405.6) 329.61,360.61 273,304 273,106 284.63,94.37 v1(361.81,94.37)
  Bottom Electrical w8: v1(361.81,94.37) TP12.1
BLE_RTS_MCU_CTS: U1.8 U4.12 | length 1191.7
  Top Electrical w8: U1.8 v1(128.45,1195.27) ; U4.12 366.18,492.53 v1@395.36,463.35
  Inner Layer 1 w8: v1(128.45,1195.27) 368.45,955.27 v1(368.45,920.27)
  Bottom Electrical w8: v1(368.45,920.27) 371.61,917.11 371.61,489.6 v1(396.61,464.6)
BLE_RX_MCU_TX: U1.4 U4.9 | length 1252.7
  Top Electrical w8: U1.4 -112.8,1337.01 -102.39,1326.6 v1@-102.39,1322.6 ; U4.9 288.8,470.29 319.61,439.48 316.72,436.6 v1(314.61,436.6)
  Inner Layer 1 w8: v1(-18.39,995.6) -15.68,992.88 -15.68,663.25 206.63,440.94 310.26,440.94 v1(314.61,436.6)
  Bottom Electrical w8: v1(-102.52,1325.47) -102.52,1258.72 -21.52,1177.72 v1@-21.52,1003.72
BLE_TX_MCU_RX: U1.5 U4.10 | length 1294
  Top Electrical w8: U1.5 -97.37,1301.57 v1(-52.39,1256.6) ; U4.10 308.48,476.72 323.73,461.47 323.85,461.47 334.32,451.01 339.96,451.01 360.61,430.36 v1(360.61,420.6)
  Inner Layer 1 w8: v1(10.61,972.6) 10.61,668.6 157.61,521.6 263.37,521.6 360.61,424.36 v1(360.61,420.6)
  Bottom Electrical w8: v1(-52.39,1256.6) 10.61,1193.6 v1(10.61,972.6)
BLE_WKUP: U1.20 U4.7 | length 1312.9
  Top Electrical w8: U4.7 249.43,464.66 261.86,452.23 261.86,415.82 v1(269.54,408.14)
  Inner Layer 1 w8: v1(269.54,408.14) 292.83,408.14 325.37,375.6 446.92,375.6 493.39,422.07 493.39,600.61 435.38,658.63 435.38,846.35 435.45,846.42 435.45,971.27 348.38,1058.34 348.38,1245.05 v1(291.5,1301.93)
CRYPTO_SCL: R6.2 U3.6 U4.14 | length 859.4
  Top Electrical w8: U4.14 403.54,543.72 415.99,531.27 422.45,531.27 422.45,522.39 435.45,509.39 447.58,497.26 447.58,448.79 R6.2
  Bottom Electrical w8: v1(420.45,530.27) 416.99,530.27 393.43,553.83 393.43,904.12 439.9,950.6 533.61,950.6 575.81,908.39 621.98,908.39 628.76,901.61 U3.6
CRYPTO_SDA: R7.2 U3.5 U4.13 | length 833
  Top Electrical w8: U4.13 392.92,524.03 398.45,518.5 v1(398.45,506.27) 416.13,506.27 431.71,490.68 431.71,410.5 447.61,394.6 447.61,374.09 R7.2
  Bottom Electrical w8: v1(398.45,506.27) 433.27,506.27 447.97,520.97 447.97,907.48 475.09,934.6 520.61,934.6 573.28,881.93 U3.5
DEBUG_RXD: TP4.1 U4.32 | length 681
  Top Electrical w8: v1(191.16,816.54) 210.06,797.64 U4.32
  Inner Layer 2 w8: v1(191.16,816.54) 211.63,796.06 610.84,796.06 751,936.22 v1(753.36,936.22)
DEBUG_TXD: TP3.1 U4.31 | length 710.6
  Top Electrical w8: v1(217.14,844.88) 229.74,832.28 U4.31
  Inner Layer 2 w8: v1(217.14,844.88) 217.14,844.09 248.64,812.6 568.32,812.6 692.32,936.6 v1(692.32,949.61)
  Bottom Electrical w8: TP3.1 692.32,997.64 v1(692.32,949.61)
GND: C1.2 C2.2 C3.1 C4.1 C5.1 C6.2 C7.1 C8.2 C9.2 C10.2 C12.1 C13.1 C14.2 C15.1 C16.2 C17.2 C18.1 C19.2 C20.2 C21.1 C22.1 C23.1 C24.2 J1.1 J2.3 J2.5 J2.9 R2.2 SW1.4 TP2.1 TP11.1 U1.1 U1.9 U1.13 U1.24 U2.2 U3.4 U3.9 U4.5 U4.18 U4.35 U4.42 U4.49 U5.9 U5.18 U5.20 U6.1 U6.7 U7.1@-353.88,1096.22 U7.4 | length 2788.5
  Top Electrical w7.6: v1(594.55,723.06) 602.54,723.06 612.34,713.27 612.34,703.48 U5.9@612.79,703.03 ; U5.9 U5.9@612.79,703.03 ; 612.79,708.21 U5.9@612.79,703.03
  Top Electrical w7.87: C6.2 -18.39,392.6 v1(2.61,371.6) ; U5.20 644.28,813.07 651.81,820.6 701.12,820.6 v1(706.45,815.27)
  Top Electrical w8: U7.4@-304.67,1165.12 -300.52,1169.27 v1(-273.55,1169.27) ; v1(57.45,828.27) v1@57.66,828.48 ; v1(88.45,804.27) 89.45,804.27 v1@89.94,803.78 ; v1(96.45,1118.27) 96.45,1120.87 96.5,1120.93 v1@97.18,1120.25 ; U4.42 159.74,642.14 170.45,652.85 U4.49@170.45,656.93 ; U4.35 151,720.88 v2(239.58,632.3) ; C13.1 210.06,456.67 U4.5 210.06,602.77 v2(239.58,632.3) ; U4.49@239.58,612.61 v2(239.58,632.3) ; U4.18 249.43,622.46 v2(239.58,632.3) ; U5.18 v1@699.89,788.54
  Top Electrical w15: C23.1 v1@-353.29,1290.72 ; C24.2@-303.29,1273.07 v1@-303.29,1300.72 ; v1(-230.55,893.93) -230.55,890.98 v1@-227.09,887.52 ; v1@-227.09,886.73 U2.2@-187.43,886.73 ; v1@-105.5,533.8 C9.2@-81.13,533.8 ; v1(-81.55,1076.93) U1.9@-49.55,1076.93 ; C7.1@-80.5,491.93 C7.1@-79.5,490.93 ; v1(-52.55,816.27) -52.55,817.87 -50.5,819.93 C1.2 ; U1.13 v1@97.18,1120.25 ; v1(188.45,366.93) 187.3,368.08 C14.2 C14.2@192.18,398.36
  Top Electrical w15.75: U7.1@-353.88,1096.22 -353.88,1044.31 v1(-350.5,1040.93) ; v1(-241.55,1169.27) -243.21,1169.27 -245.55,1171.61 -238.89,1178.27 v1@-234.55,1173.93 ; v1(-45.39,1015.6) -44.55,1016.44 U1.9 ; v1(53.45,148.46) 55.47,146.44 J2.9 80.61,145.6 80.61,85 88.01,77.6 146.61,77.6 147.61,78.6 148.61,77.6 180.45,109.44 J2.5@180.45,145.44 ; J2.5@184.45,145.44 184.45,167.81 J2.3@234.45,167.81 ; C15.1 518.08,534.98 C16.2 521.98,534.93 v1(548.45,534.93) ; v1@584.5,560.66 C20.2 ; v1(634.5,566.93) 634.73,566.93 635.12,567.32 C18.1 ; v1@682.47,564.96 C17.2@682.47,593.07
  Top Electrical w20: v1(-161.5,1475.93) -161.87,1475.55 U1.1 -108.12,1443.31 v1(-107.5,1443.93) ; v1(-105.5,491.93) C7.1@-80.5,491.93 ; v1@57.66,828.48 C12.1 v1@89.94,803.78 ; C14.2@192.18,398.36 C13.1 ; v1(275.5,1443.93) 276.13,1443.31 U1.24 338.13,1474.31 v1(337.5,1474.93)
  Bottom Electrical w7.6: SW1.4@-363.92,1091.68 SW1.4@-363.92,1086.73 ; v1(-350.5,1040.93) -363.92,1054.35 SW1.4@-363.92,1086.73 ; SW1.4@-285.18,1091.68 -290.13,1086.73 SW1.4@-363.92,1086.73
  Bottom Electrical w8: v1(-273.55,1169.27) -268.89,1169.27 v1@-268.68,1169.05 ; v1@593.45,719.93 C19.2 624.79,735.25 609.08,750.96 U3.4
  Bottom Electrical w15.75: SW1.4@-364.39,1092.16 SW1.4@-363.92,1091.68 ; U6.7 -301.35,1343.13 -315.55,1328.93 -315.55,1326.93 v1(-317.55,1324.93) -326.94,1315.54 U6.1 -326.94,1222.65 v1(-273.55,1169.27) ; C21.1 C22.1 -210.55,1470.36 v1(-209.12,1471.8) -209.12,1474.05 v1@-207.39,1475.77 ; v1(0,85) TP11.1 ; v1(306.45,1498.27) C3.1 v1(335.45,1531.27)
  Bottom Electrical w19.68: U3.9 654.03,840.26 C5.1 v1(706.45,815.27)
  other v1: 164.45,360.27 -136.39,391.6 -114.39,532.6 -168.55,533.93 -141.55,533.93 574.66,535.06 582.83,562.33 682.5,564.93 -363.55,758.27 -325.14,759.57 -284.55,759.27 695.45,789.93 -327.39,801.6 -116.5,818.93 -88.5,818.93 -258.55,893.27 -251.55,926.93 -292.58,929.13 -312.27,956.69 -217.55,1169.27 198.45,1241.27 245.5,1286.93 141.5,1287.93 -354.5,1291.93 -304.5,1301.93 56.5,1302.93 198.45,1327.27 141.5,1388.93 54.5,1390.93 252.5,1391.93
  other v2: 334.07,537.81 145.09,585.05 192.34,585.05 239.58,585.05 286.83,585.05 334.07,585.05 145.09,632.3 192.34,632.3 286.83,632.3 334.07,632.3 145.09,679.54 192.34,679.54 239.58,679.54 286.83,679.54 334.07,679.54 145.09,726.79 192.34,726.79 239.58,726.79 286.83,726.79
LED0: R11.1 U4.23 | length 137.7
  Top Electrical w8: U4.23 398.01,720.88 429.61,752.48 R11.1
LED1: R10.1 U4.24 | length 86.4
  Top Electrical w8: U4.24 379.35,764.93 379.61,765.19 R10.1
LED2: R9.1 U4.28 | length 66
  Top Electrical w8: R9.1@271.5,830.93 271.5,810.22 288.8,792.93 U4.28
MCU_VCC: C7.2 C9.1 C12.2 C15.2 C16.1 J2.1 L2.1 R29.2 TP5.1 U4.17 U4.36 U4.44 | length 689.6
  Top Electrical w8: -38.16,524.27 C9.1@-28.63,533.8 ; v1@278.45,368.27 284.57,362.15 L2.1 ; U4.17@392.57,602.77 392.57,603.46 433.76,603.46 460.91,576.32 C15.2 ; v1@547.06,576.31 v1(547.45,575.93)
  Top Electrical w10: C9.1@-28.63,533.8 3.13,533.8 72.1,602.77 U4.44 ; v1(93.45,865.27) 123.19,865.27 123.5,865.58 160.61,828.48 C12.2 ; U4.36 131.32,826.91 C12.2@132.46,828.05 ; U4.17 U4.17@392.57,602.77
  Top Electrical w15: C7.2@-38.16,485.93 -38.16,524.27
  Top Electrical w20: J2.1@280.45,145.44 278.61,143.6 282.21,140 v1(310,140) ; C15.2 C16.1 v1@547.06,576.31
  Bottom Electrical w20: v1(180,65) 180,120 TP5.1@190,130
  other v1: 270.68,372.44 294.61,372.6 2.45,494.27 1.45,517.27 549.45,606.27 157.45,824.27 119.45,864.27 156.5,866.93
NetC17_1: C17.1 U5.10 | length 90
  Top Electrical w8: U5.10 628.54,677.71 642.65,663.6 655.25,663.6 C17.1@682.47,636.38
NetD2_1: D2.1 R9.2 | length 960.6
  Top Electrical w7.87: D2.1 -292.39,1542.61 v1(-291.39,1543.6) ; v1(251.5,911.93) 251.5,896.17 R9.2
  Inner Layer 1 w7.87: v1(-291.39,1543.6) -291.39,1486.6 -229.39,1424.6 -167.97,1424.6 -64.69,1321.31 -64.6,1321.31
  Inner Layer 1 w8: -64.6,1321.31 251.5,1005.21 v1(251.5,911.93)
NetD2_2: D2.2 D3.2 D4.2 R24.1 R31.1 | length 245.9
  Top Electrical w15: D4.2 D3.2 D2.2 -351.44,1559.55 v1(-343.39,1567.6)
  Bottom Electrical w15: v1(-343.39,1567.6) -343.39,1565.6 -320.39,1542.6 R24.1
NetD3_1: D3.1 R10.2 | length 1024.7
  Top Electrical w7.87: D3.1 -273.28,1456.71 -262.2,1467.79 -262.2,1497.46 -241.07,1518.6 -204.88,1518.6 v1(-189.55,1503.27) ; v1(338.45,902.27) 351.44,902.27 R10.2
  Inner Layer 1 w7.87: v1(-189.55,1503.27) -185.31,1499.02 -185.31,1464.38 338.45,940.63 v1(338.45,902.27)
NetD4_1: D4.1 R11.2 | length 1000.2
  Top Electrical w7.87: D4.1 -292.39,1340.76 -281.36,1329.74 -218.02,1329.74 v1(-217.55,1329.27) ; v1(227.45,940.27) 231.26,944.08 410.64,944.08 429.61,925.11 R11.2
  Inner Layer 1 w7.87: v1(-217.55,1329.27) 17.19,1094.52 73.19,1094.52 v1(227.45,940.27)
NetJ1_2: J1.2 J3.2@-321.39,581.6 R30.1 TP1.1 | length 567.1
  Bottom Electrical w50: J3.2@-325.5,577.93 -325.5,578.8 J3.2@-318.6,578.8 ; J3.2@-321.39,581.6 J3.2@-318.6,578.8 ; J1.2@193.41,475.83 161.89,475.83 58.91,578.8 -187.14,578.8 -188.01,577.93 -317.72,577.93 J3.2@-318.6,578.8
NetJ3_1: J3.1@-321.39,681.6 R30.2 SW1.1 | length 505.4
  Bottom Electrical w50: J3.1@-325.5,677.93 -202.82,677.93 -164.91,715.85 -164.91,931.47 -166.3,932.87 -166.3,940.32 -201.13,975.16 SW1.1@-255.97,975.16
NetL1_1: L1.1 U4.43 | length 138.5
  Top Electrical w8: L1.1@-37.43,625.53 -34.35,622.46 U4.43
NetR4_1: R4.1 U4.19 | length 80.6
  Top Electrical w8: U4.19 408.45,642.14 422.31,628.28 R4.1
NetR5_1: R5.1 U4.20 | length 81.6
  Top Electrical w8: U4.20 414.34,661.83 430.78,678.28 R5.1
NetR22_1: R22.1 U5.7 | length 394
  Top Electrical w7: v1(563.61,675.6) 581.29,693.28 U5.7
  Top Electrical w8: R22.1 586.23,929.22 586.61,929.6 v1(586.61,932.6)
  Inner Layer 1 w8: v1(563.61,675.6) 606.61,675.6 634.61,703.6 634.61,884.6 v1(586.61,932.6)
NetR23_1: R23.1 U5.21 | length 53
  Top Electrical w7.87: U5.21 628.54,832.53 638.61,842.6 R23.1
NetR28_1: R28.1 U4.16 | length 206.8
  Top Electrical w8: U4.16 402.91,583.09 407.41,587.59 427.19,587.59 446.32,568.46 446.32,520.97 ; R28.1 475.2,492.09 465.11,502.18 ; 446.32,520.97 465.11,502.18 ; 446.32,520.97 465.11,502.18
NetTP7_1: TP7.1 U1.2 | length 235
  Top Electrical w8: U1.2 -99.02,1407.87 -83.62,1423.27 -83.62,1493.62 -97.44,1507.44 v1(-97.44,1524.41)
  Bottom Electrical w8: TP7.1@-139.96,1522.05 -99.8,1522.05 v1(-97.44,1524.41)
NetTP8_1: TP8.1 U1.3 | length 310.1
  Top Electrical w8: U1.3 -60.43,1372.44 -10.83,1422.05 -10,1422.87 v1(-10,1520)
  Bottom Electrical w8: TP8.1@-49.41,1522.05 -35.24,1522.05 -33.19,1520 v1(-10,1520)
PA00: C6.1 U4.1 XC1.1 | length 215.1
  Top Electrical w8: C6.1@-48.02,422.22 -29.64,440.6 32.19,440.6 XC1.1@36.4,444.81 ; XC1.1@39.89,441.31 53.5,454.93 108.5,454.93 131.32,477.74 U4.1
PA01: C10.1 U4.2 XC1.2 | length 187
  Top Electrical w8: C10.1@57.92,319.29 71.61,332.98 71.61,351.6 100.43,380.42 XC1.2@100.43,380.78 ; XC1.2@120.5,397.29 120.5,440.15 151,470.65 U4.2
R\E\S\E\T\: J2.10 TP10.1 U4.40 | length 1206.2
  Top Electrical w8: v1(-39.55,783.27) -39.34,783.48 44.72,783.48 64.61,763.6 64.61,696.72 79.82,681.51 U4.40 ; J2.10@80.45,-8.1 80.45,48.44 v1(80.61,48.6) ; v1@84.45,48.6 v1@84.45,54.6
  Inner Layer 1 w8: v1(-39.55,783.27) -39.55,658.99 125.73,493.71 125.73,135.73 80.61,90.61 v1(80.61,48.6)
  Bottom Electrical w8: TP10.1 48.6,48.6 v1(80.61,48.6)
RTC_CLKN: U1.19 XC2.2 | length 342.5
  Top Electrical w10: XC2.2@265.61,1022.48 295.61,1052.48 295.61,1127.48 250.61,1172.48 250.61,1232.48 284.27,1266.14 U1.19
RTC_CLKP: U1.18 XC2.1 | length 310.2
  Top Electrical w10: U1.18 281.71,1230.71 270.61,1219.61 270.61,1177.76 313.48,1134.88 313.48,1059.61 XC2.1@356.16,1016.93
SENSOR_AP_INT: R12.2 U4.15 U5.12 | length 500.7
  Top Electrical w7.87: U4.15 v1@409.9,563.4 ; U5.12 660.03,693.99 670.39,693.99 v1(681.45,682.93) ; v1@409.9,563.4 410.21,563.72 v1(417.3,563.72) 416.98,563.4 v1@409.9,563.4
  Inner Layer 2 w7.87: v1(417.3,563.72) 417.3,640.29 457.61,680.6 527.61,680.6 549.34,702.33 581.61,702.33 601.01,682.93 v1(681.45,682.93)
  Bottom Electrical w7.87: R12.2 641.37,659.85 664.45,682.93 v1(681.45,682.93)
SENSOR_I2C_SCL: R14.2 U4.22 U5.23 U6.4 U7.5 | length 1502.8
  Top Electrical w8: U7.5 -328.29,1157.29 -320.48,1149.48 -320.48,1149.37 -313.52,1142.42 -313.42,1142.42 -308,1137 -279,1137 ; U4.22 408.32,701.2 456.45,749.32 456.45,848.93 v1(481.45,873.93) 482.78,872.6 559.78,872.6 585.45,846.93 585.45,850.16 586.41,850.16 586.41,828.02 597.04,817.39 U5.23
  Inner Layer 2 w8: v1(-115.39,1111.6) -82.46,1111.6 104.68,924.46 187.68,924.46 238.21,873.93 v1(481.45,873.93)
  Bottom Electrical w8: v1(-265,1137) -201.28,1137 -198.55,1134.27 ; U6.4 -250.17,1240.88 -185.55,1176.27 -185.55,1142.44 ; -177.38,1134.27 -185.55,1142.44 ; v1(-115.39,1111.6) -138.06,1134.27 -198.55,1134.27 ; -198.55,1134.27 -193.72,1134.27 -185.55,1142.44
SENSOR_I2C_SDA: R13.2 U4.21 U5.24 U6.3 U7.2 | length 1524.8
  Top Electrical w7.87: U7.2 -328.29,1118.71 v1(-328,1119) ; U4.21 411.66,681.51 449.35,719.86 452.41,722.93 v1(483.45,722.93) 482.45,723.93 R13.2 506.65,756.93 554.45,804.73 577.5,804.73
  Inner Layer 1 w7.87: v1(-328,1119) -328,1244.61 -328.07,1244.68 -272.55,1300.2 v1(-272.55,1305.93)
  Inner Layer 2 w7.87: v1(-328,1119) -328,1110.33 -204.87,987.2 -170,987.2 48.09,769.11 437.27,769.11 v1(483.45,722.93)
  Bottom Electrical w7.87: U6.3@-274.55,1265.31 v1@-274.55,1305.93
SENSOR_UV_ALS_INT: U4.27 U7.3 | length 854.6
  Top Electrical w8: U7.3 -203.77,1096.22 -163.19,1136.8 -84.02,1136.8 v1(-83.55,1137.27) ; U4.27 v1@308.48,902.27
  Inner Layer 2 w8: v1(-83.55,1137.27) -55.05,1137.27 103.8,978.42 232.02,978.42 306.56,903.88 v1@308.06,903.88
  other v1: 306.45,902.27
SWCLK: J2.4 TP9.1 U4.45 | length 778.5
  Top Electrical w8: v1(42.45,512.27) 42.45,549.25 76.28,583.09 U4.45
  Inner Layer 2 w8: v1(42.45,512.27) 42.45,468.27 57.45,453.27 176.45,453.27 213.45,416.27 213.45,68 v1@220.67,60.78
  Bottom Electrical w8: TP9.1@181.45,-7.1 181.45,6.45 v1(225,50)
SWDIO: J2.2 TP6.1 U4.46 | length 851.6
  Top Electrical w8: v1(66.45,490.27) 66.45,542.96 86.89,563.4 U4.46 ; J2.2@280.45,-8.1 J2.2@280.45,-7.1 ; J2.2 283.55,-5 v1(315,-5)
  Inner Layer 2 w8: v1(66.45,490.27) 184.73,490.27 240,435 240,70 v1(315,-5)
  Bottom Electrical w8: v1@320,0 v1(315,-5) 355,-5 TP6.1@360,0
VBAT: C2.1 C4.2 C5.2 R1.1 R31.2 SW1.2 U1.6 U2.1 U2.3 U3.8 | length 2047.1
  Top Electrical w8: R1.1 -196.55,824.93 -180.55,840.93 -180.55,860.05 -181.43,860.93 -153.87,860.93 -148.37,866.42 -148.37,898.75 -160.55,910.93
  Top Electrical w15: v1(-237.55,1302.27) -235.89,1302.27 -235.55,1301.93 C4.2 -232.34,1266.14 U1.6
  Top Electrical w39.37: -190.5,1026.93 -183.5,1033.93 -178.5,1028.93
  Inner Layer 2 w15: v1(-246.39,1542.6) -275.39,1513.6 -275.39,1346.6 -262.1,1333.3 -261.21,1333.3 -237.55,1309.64 v1(-237.55,1302.27) -237.55,1257.27 -185.93,1205.64 -185.93,1074.3 -170.55,1058.93 v1(-143.5,1058.93)
  Bottom Electrical w8: v1(-141.5,1028.93) -129.43,1016.86 ; U3.8 706.12,881.93 C5.2
  Bottom Electrical w10: -129.43,1016.86 -129.43,959.14 -102.55,932.27 136.45,932.27 186.11,981.93 582.84,981.93 610.62,954.14 651.98,954.14 706.45,899.67 C5.2
  Bottom Electrical w15: R31.2 -273.15,1515.84 v1(-246.39,1542.6)
  Bottom Electrical w39.37: SW1.2@-256.87,1034.21 -146.78,1034.21 v1(-141.5,1028.93)
VCC: C1.1 C3.2 C18.2 C19.1 C20.1 C21.2 C22.2 C23.2 C24.1 R6.1 R7.1 R12.1 R13.1 R14.1 R22.2 R23.2 R24.2 R27.1 R29.1 U1.22 U2.5 U5.8 U5.13 U6.2 U6.5 U6.6 U6.8 U7.6 | length 1439.1
  Top Electrical w8: C23.2 -307.39,1225.83 C24.1 v1(-282.5,1224.93) ; U7.6@-351.91,1165.12 C23.2@-351.91,1224.45 ; R27.1 390.69,342.02 399.12,333.6 482.69,333.6 494.69,345.6 R7.1 494.69,396.93 R6.1 520.69,447.51 521.46,446.75 v1(521.46,444.09) ; C20.1 584.5,660.5 597.04,673.03 U5.8 ; U5.13 691.32,709.8 v1(700.45,718.93)
  Top Electrical w15: U1.22 380.45,1372.44 395.45,1387.44 v1(395.45,1465.27) ; R13.1 487.65,809.37 487.65,841.93 v1(492.45,841.93) 497.45,846.93 R14.1@538.2,846.93 ; v1(495.61,902.6) 534.98,902.6 R22.2 ; v1(557.5,637.93) C20.1 ; C20.1@585.53,638.96 C18.2 ; R23.2 638.61,919.6 636.61,921.6 638.61,923.6 638.61,924.6 v1(639.61,925.6)
  Bottom Electrical w8: U6.8 -326.94,1394.54 -309.55,1411.93 C21.2 ; U6.2 -301.35,1243.78 v1(-282.5,1224.93)
  Bottom Electrical w15: R24.2 -317.35,1462.29 -298.28,1481.37 -244.62,1481.37 v1(-238.39,1487.6) ; U6.6@-272.55,1362.55 -272.17,1362.93 -250.54,1362.93 U6.5 -250.17,1381.54 -259.55,1390.93 -259.55,1410.93 C21.2 C22.2 -210.55,1387.93 v1@-211.55,1386.93 ; C3.2 394.45,1494.27 394.45,1466.27 v1(395.45,1465.27) ; v1@558.5,638.93 v1(557.5,637.93) 585.18,610.25 R12.1 ; C19.1@662.45,718.93 C19.1@668.1,718.93 ; C19.1 699.45,719.93 v1(700.45,718.93)
  other v1: -96.55,962.27 -68.55,962.27 -42.55,962.27 -218.55,1362.27 -218.55,1385.27
VCC_MCU_VDDANA: C13.2 C14.1 L2.2 U4.6 | length 150.6
  Top Electrical w8: C14.1@229.74,393.48 229.74,478.48
  Top Electrical w10: 229.74,478.48 U4.6
  Top Electrical w19.68: L2.2 230.61,344.43 C14.1 C14.1@229.74,393.48
VDDCORE: C8.1 L1.2 U4.41 | length 266.8
  Top Electrical w8: L1.2@-37.43,692.46 46.04,692.46 76.67,661.83 U4.41
  Top Electrical w19.68: C8.1@-154.87,697.85 L1.2@-38.04,697.85
Y2: CS1.1 R4.2 | length 517.3
  Top Electrical w8: R4.2 508.05,628.28 v1(525.63,645.85)
  Inner Layer 1 w8: v1(525.63,645.85) 525.63,675.91 543.32,693.6 543.32,932.87 551.06,940.6 v1(551.06,1033.86)
  Bottom Electrical w8: 543.61,1118.6 549.61,1112.6 v1@549.61,1033.86
Y3: CS2.1 R5.2 | length 738.4
  Top Electrical w8: R5.2 504.35,678.28 519.45,693.37 v1(519.45,706.93)
  Inner Layer 1 w8: v1(443.13,1311.81) 420.61,1289.29 420.61,1050.83 520,951.43 520,707.9 519.45,707.35 v1(519.45,706.93)
  Bottom Electrical w8: v1(443.13,1311.81) 447.06,1315.75 486.43,1315.75
Y9: CS3.1 R28.2 | length 441.7
  Top Electrical w8: R28.2 543.27,476.93 v1(556.89,490.55) v1@549.73,490.55
  Bottom Electrical w8: -90.55,307.27 77.45,307.27 81.45,303.27 ; v1(556.89,490.55) 560.04,490.55 569.49,500 767.13,500 771.85,495.28
pads on no net: J2.6 J2.7 J2.8 J3.1@-321.39,681.6 J3.2@-321.39,581.6 SW1.0 SW1.3 U1.10 U1.11 U1.12 U1.14 U1.15 U1.16 U1.21 U1.23 U2.4 U3.1 U3.2 U3.3 U3.7 U4.4 U4.25 U4.26 U4.29 U4.30 U4.33 U4.34 U4.37 U4.38 U4.39 U4.47 U4.48 U5.1 U5.2 U5.3 U5.4 U5.5 U5.6 U5.11 U5.14 U5.15 U5.16 U5.17 U5.19 U5.22 U7.1@-373.57,1096.22

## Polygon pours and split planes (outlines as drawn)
Y9 on Bottom Electrical "PROX" (solid, remove dead copper, pour order 4): 784.69,295.28 760.36,295.28 733.51,295.28 733.51,765.35 760.36,765.35 784.69,765.35
Y9 on Bottom Electrical "PROX" (solid, remove dead copper, pour order 5): -385.73,470.68 -334.55,470.68 -334.55,294.49 -385.73,294.49
GND on Ground Plane (GND) (split plane): -188.58,1557.94 -186.52,1556.36 -184.13,1555.37 -181.56,1555.03 357.81,1555.03 360.38,1555.37 362.77,1556.36 364.23,1557.48 440.61,1557.48 440.61,1027.48 780.68,1027.48 780.68,320.38 780.59,319.73 780.62,319.73 780.31,315.77 779.3,311.56 777.64,307.55 775.37,303.85 772.55,300.55 769.25,297.73 765.56,295.47 761.55,293.81 759.82,293.39 318.11,293.39 315.54,293.05 313.15,292.06 311.09,290.48 309.51,288.43 308.52,286.03 308.18,283.46 308.18,204.72 308.52,202.16 309.51,199.76 311.09,197.7 313.15,196.13 315.54,195.14 318.11,194.8 497,194.8 497,-61.83 -133.11,-62.6 -133.11,194.8 81.89,194.8 84.46,195.14 86.85,196.13 88.91,197.7 90.49,199.76 91.48,202.16 91.82,204.72 91.82,283.46 91.48,286.03 90.49,288.43 88.91,290.48 86.85,292.06 84.46,293.05 81.89,293.39 -353.45,293.39 -354.09,293.48 -354.09,293.45 -358.05,293.76 -362.26,294.77 -366.27,296.43 -369.97,298.7 -373.27,301.52 -376.09,304.82 -378.35,308.52 -380.01,312.52 -380.62,315.06 -380.62,1559.05 -189.43,1559.05
MCU_VCC on Power Plane (VCC) (split plane): 393.49,948.8 393.49,820.93 393.69,819.39 394.29,817.95 395.24,816.72 396.47,815.77 397.91,815.18 399.45,814.97 514.05,814.97 514.05,643.37 514.25,641.83 514.6,640.99 514.85,640.4 515.79,639.16 564.49,590.46 564.49,541.74 491.24,468.48 490.29,467.25 490.04,466.65 489.69,465.81 489.49,464.27 489.49,293.39 318.11,293.39 315.54,293.05 313.15,292.06 311.09,290.48 309.51,288.43 308.52,286.03 308.18,283.46 308.18,204.72 308.52,202.16 309.51,199.76 311.09,197.7 313.15,196.13 315.54,195.14 318.11,194.8 497,194.8 497,-61.83 -133.11,-62.6 -133.11,194.8 81.89,194.8 84.46,195.14 86.85,196.13 88.91,197.7 90.49,199.76 91.48,202.16 91.82,204.72 91.82,283.46 91.48,286.03 90.49,288.43 88.91,290.48 86.85,292.06 84.46,293.05 81.89,293.39 -66.54,293.39 -66.54,888.03 46.74,1001.31 340.98,1001.31
VCC on Power Plane (VCC) (split plane): -188.58,1557.94 -186.52,1556.36 -184.13,1555.37 -181.56,1555.03 357.81,1555.03 360.38,1555.37 362.77,1556.36 364.23,1557.48 440.61,1557.48 440.61,1027.48 780.68,1027.48 780.68,320.38 780.59,319.73 780.62,319.73 780.31,315.77 779.3,311.56 777.64,307.55 775.37,303.85 772.55,300.55 769.25,297.73 765.56,295.47 761.55,293.81 759.82,293.39 501.4,293.39 501.4,461.8 574.66,535.06 575.61,536.29 576.2,537.73 576.41,539.27 576.41,592.93 576.2,594.47 575.61,595.91 574.66,597.14 525.96,645.84 525.96,818.8 526.2,819.39 526.41,820.93 526.2,822.47 525.61,823.91 524.66,825.14 523.43,826.09 521.99,826.68 520.45,826.89 405.4,826.89 405.4,951.27 405.2,952.81 404.61,954.25 403.66,955.48 347.66,1011.48 346.43,1012.43 345.83,1012.67 344.99,1013.02 343.45,1013.22 44.28,1013.22 42.73,1013.02 41.72,1012.6 41.3,1012.43 40.06,1011.48 -76.71,894.71 -77.65,893.47 -77.9,892.88 -78.25,892.04 -78.45,890.5 -78.45,293.39 -353.45,293.39 -354.09,293.48 -354.09,293.45 -358.05,293.76 -362.26,294.77 -366.27,296.43 -369.97,298.7 -373.27,301.52 -376.09,304.82 -378.35,308.52 -380.01,312.52 -380.62,315.06 -380.62,1559.05 -189.43,1559.05

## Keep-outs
Power Plane (VCC):
  lines w8: -390.39,1821.6 cw(c-352.89,1821.1) -360.25,1857.87
Keep-Out Layer:
  lines w8: -390.5,311.7 -390.5,1857.93 -181.56,1857.93 -181.56,1565 357.81,1565 357.81,1857.93 790.61,1857.93 790.61,309.6 764.28,283.27 320,283.27 320,205.8 510,205.8 510,-73.88 -145,-73.88 -145,205.63 80,205.63 80,283.27 -362.06,283.27 -390.5,311.7

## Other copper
Top Electrical:
  rectangle net GND: -272.55,833.37 -220.23,921.27
  rectangle net GND: -143.55,784.25 -62.55,816.27
  rectangle net GND: -287.55,965.93 -228.55,1016.93
  rectangle net GND: -330.18,915.93 -228.55,976.93
  rectangle net VCC: -136.55,900.93 -30.55,977.27
  rectangle net GND: -159.24,803.93 -56.5,831.93
  rectangle net GND: -76.5,803.93 -24.55,882.93
  rectangle net VBAT: -176.5,1009.93 -116.5,1077.93
  rectangle net VBAT: -210.5,904.93 -155.5,1057.93
  rectangle net VCC: -136.5,896.93 49.42,948.08
  rectangle net MCU_VCC: 116.5,810.24 168.5,939.68
  rectangle net NetJ3_1: -360.5,647.93 -209.39,710.93
  rectangle net NetJ1_2: -366.5,544.27 -213.39,631.5
  rectangle net GND: -182.55,521.93 -134.83,644.88
  rectangle net GND: -158.55,521.93 -59.39,555.93
  rectangle net MCU_VCC: 75.3,853.27 124.3,939.68
  rectangle net MCU_VCC: 535.45,560.27 560.45,614.27
  region net MCU_VCC: 560.45,559.27 560.45,594.27 512.05,594.27 512.05,559.27
  region net GND: 586.45,518.32 586.45,548.27 472.45,548.27 472.45,518.32
  rectangle net GND: 174.87,359.27 204.45,440.27
  rectangle net GND: 151.45,332.27 204.45,371.27
  rectangle net MCU_VCC: 261.45,319.65 308.19,388.27
  rectangle net MCU_VCC: -52.39,482.6 16.61,510.6
  region net MCU_VCC: -11.55,477.27 -11.55,543.27 -45.55,543.27 -45.55,477.27
  region net MCU_VCC: 16.45,484.27 16.45,550.6 -20.55,550.6 -20.55,484.27
  rectangle net GND: -253.55,1154.27 -209.55,1222.27
Bottom Electrical:
  region net Y9: -340.75,340.27 -340.75,295.28 -47.55,295.28 -47.55,340.27
  rectangle net VBAT: -170.5,1007.93 -114.5,1083.93
  region net Y9: 752.61,296.06 752.61,339.77 57.45,339.77 57.45,296.06
  rectangle net VCC: -230.55,1358.27 -172.55,1423.27
  rectangle net GND: -376.39,788.6 -278.39,814.6
Ground Plane (GND) (plane layer: these items are gaps in the copper):
  rectangle: 440.61,1027.48 790.61,1562.48
  rectangle: 350.61,1557.48 790.61,1859.02
  rectangle: -393.57,1559.05 -177.54,1861.34
Power Plane (VCC) (plane layer: these items are gaps in the copper):
  rectangle: -393.57,1559.05 -177.54,1861.34
  rectangle: 354.1,1557.48 790.61,1859.02
  rectangle: 440.61,1027.48 790.61,1574.77
  rectangle: 150.72,582.68 323.95,726.79
  lines w11.81: -72.5,281.6 -72.5,890.5 44.28,1007.27 343.45,1007.27 399.45,951.27 399.45,820.93 520.45,820.93 ; 495.09,288.08 495.45,287.72 495.45,464.27 570.45,539.27 570.45,592.93 520,643.37 520,819.93

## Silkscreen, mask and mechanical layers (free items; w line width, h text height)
Top Overlay:
  region: 774.58,1538.74 459.62,1538.74 459.62,1302.52 774.58,1302.52
  region: 774.58,1293.86 459.62,1293.86 459.62,1057.64 774.58,1057.64
  lines w4: 550.61,517.6 595.61,517.6 ; 673.61,837.6 673.61,913.6 673.61,920.6 778.61,920.6 778.61,837.6 673.61,837.6
  lines w7.87: 134,207.47 251,207.47
  text "B" at 455.45,1579.27 h200
  text "Wearable Demo" at 405.45,981.93 h58
  text "1" at 370,145 h39.37
  text "2" at 370,-30 h39.37
Bottom Overlay:
  text "c" at 512.61,1752.6 h100
  text "f" at 502.61,1668.6 h100
  text "t" at 484.61,1586.6 h100
  text "A08-2606" at 740.49,1471.65 h40
  text "p" at 513.58,1465.35 h100
  text "Rev 4" at 754.66,1414.96 h40
Top Paste:
  rectangle: 150.45,560.93 234.45,617.93
  rectangle: 246.45,560.93 334.45,617.93
  rectangle: 245.45,645.93 333.45,702.93
  rectangle: 149.45,645.93 233.45,702.93
Mechanical 1:
  lines w8: -390.55,313.71 -390.55,1821.6 ; -390.5,313.71 ccw(c-353.72,321.07) -354.22,283.57 ; -390.39,1821.6 cw(c-352.89,1821.1) -360.25,1857.87 ; -360.25,1858.27 -181.56,1858.27 -181.56,1564.96 357.81,1564.96 357.81,1857.48 754.33,1857.48 ; -353.73,283.46 81.89,283.46 81.89,204.72 -143.03,204.72 -143.03,-72.54 ; -143.03,-71.75 506.93,-71.75 ; 506.93,-72.54 506.93,204.72 318.11,204.72 318.11,283.46 760.61,283.46 ; 754.28,1857.38 cw(c753.78,1819.88) 790.55,1827.23 ; 760.36,283.32 ccw(c753,320.1) 790.5,319.6 ; 790.61,320.1 790.61,1827.6
Mechanical 2:
  circle w10: c677.61,1751.18 r98.43
  circle w10: c-286.96,1751.18 r98.43
  circle w10: c-286.96,412.6 r98.43
  circle w10: c677.61,412.6 r108.27
Drill Drawing:
  circle w10: c1835.62,810.83 r33.33
  lines w10: 1802.29,494.17 1818.96,494.17 1835.62,477.5 1852.29,494.17 1868.96,494.17 1852.29,510.83 1868.96,527.5 1852.29,527.5 1835.62,544.17 1818.96,527.5 1802.29,527.5 1818.96,510.83 1802.29,494.17 ; 1802.29,627.5 1835.62,644.17 1868.96,627.5 1852.29,660.83 1868.96,694.17 1835.62,677.5 1802.29,694.17 1818.96,660.83 1802.29,627.5 ; 1802.29,927.5 1868.96,927.5 1868.96,994.17 1802.29,994.17 1802.29,927.5
  lines w15: 1742.5,432.5 5621.47,432.5 ; 1742.5,1032.5 5621.47,1032.5 ; 2293.38,282.5 2293.38,1182.5 ; 2991.19,282.5 2991.19,1182.5 ; 4336.79,282.5 4336.79,1182.5 ; 4842.67,282.5 4842.67,1182.5 ; 1742.5,282.5 5621.47,282.5 5621.47,1182.5 1742.5,1182.5 1742.5,282.5
  text "Symbol" at 1832.5,1077.5 h72
  text "Hit Count" at 2338.38,1077.5 h72
  text "Finished Hole Size" at 3036.19,1077.5 h72
  text "Plated" at 4381.79,1077.5 h72
  text "Hole Type" at 4887.67,1077.5 h72
  text "2" at 2338.38,927.5 h60
  text "37.40mil (0.950mm)" at 3036.19,927.5 h60
  text "PTH" at 4381.79,927.5 h60
  text "Round" at 4887.67,927.5 h60
  text "2" at 2338.38,777.5 h60
  text "39.37mil (1.000mm)" at 3036.19,777.5 h60
  text "PTH" at 4381.79,777.5 h60
  text "Round" at 4887.67,777.5 h60
  text "4" at 2338.38,627.5 h60
  text "118.11mil (3.000mm)" at 3036.19,627.5 h60
  text "NPTH" at 4381.79,627.5 h60
  text "Round" at 4887.67,627.5 h60
  text "163" at 2338.38,477.5 h60
  text "12.00mil (0.305mm)" at 3036.19,477.5 h60
  text "PTH" at 4381.79,477.5 h60
  text "Round" at 4887.67,477.5 h60
  text "171 Total" at 2338.38,327.5 h60

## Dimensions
670.28,1019.68 to 750.59,961.42 on Mechanical 4
670.28,1019.68 to 750.59,961.42 on Mechanical 4
506.93,-72.54 to 361.81,0 on Mechanical 4
361.81,130 to 361.81,0 on Mechanical 4
180.91,0 to 361.81,0 on Mechanical 4
0,0 to 361.81,0 on Mechanical 4
506.93,-71.75 to 357.81,1857.48 on Mechanical 4
-390.55,313.71 to 790.61,320.1 on Mechanical 4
